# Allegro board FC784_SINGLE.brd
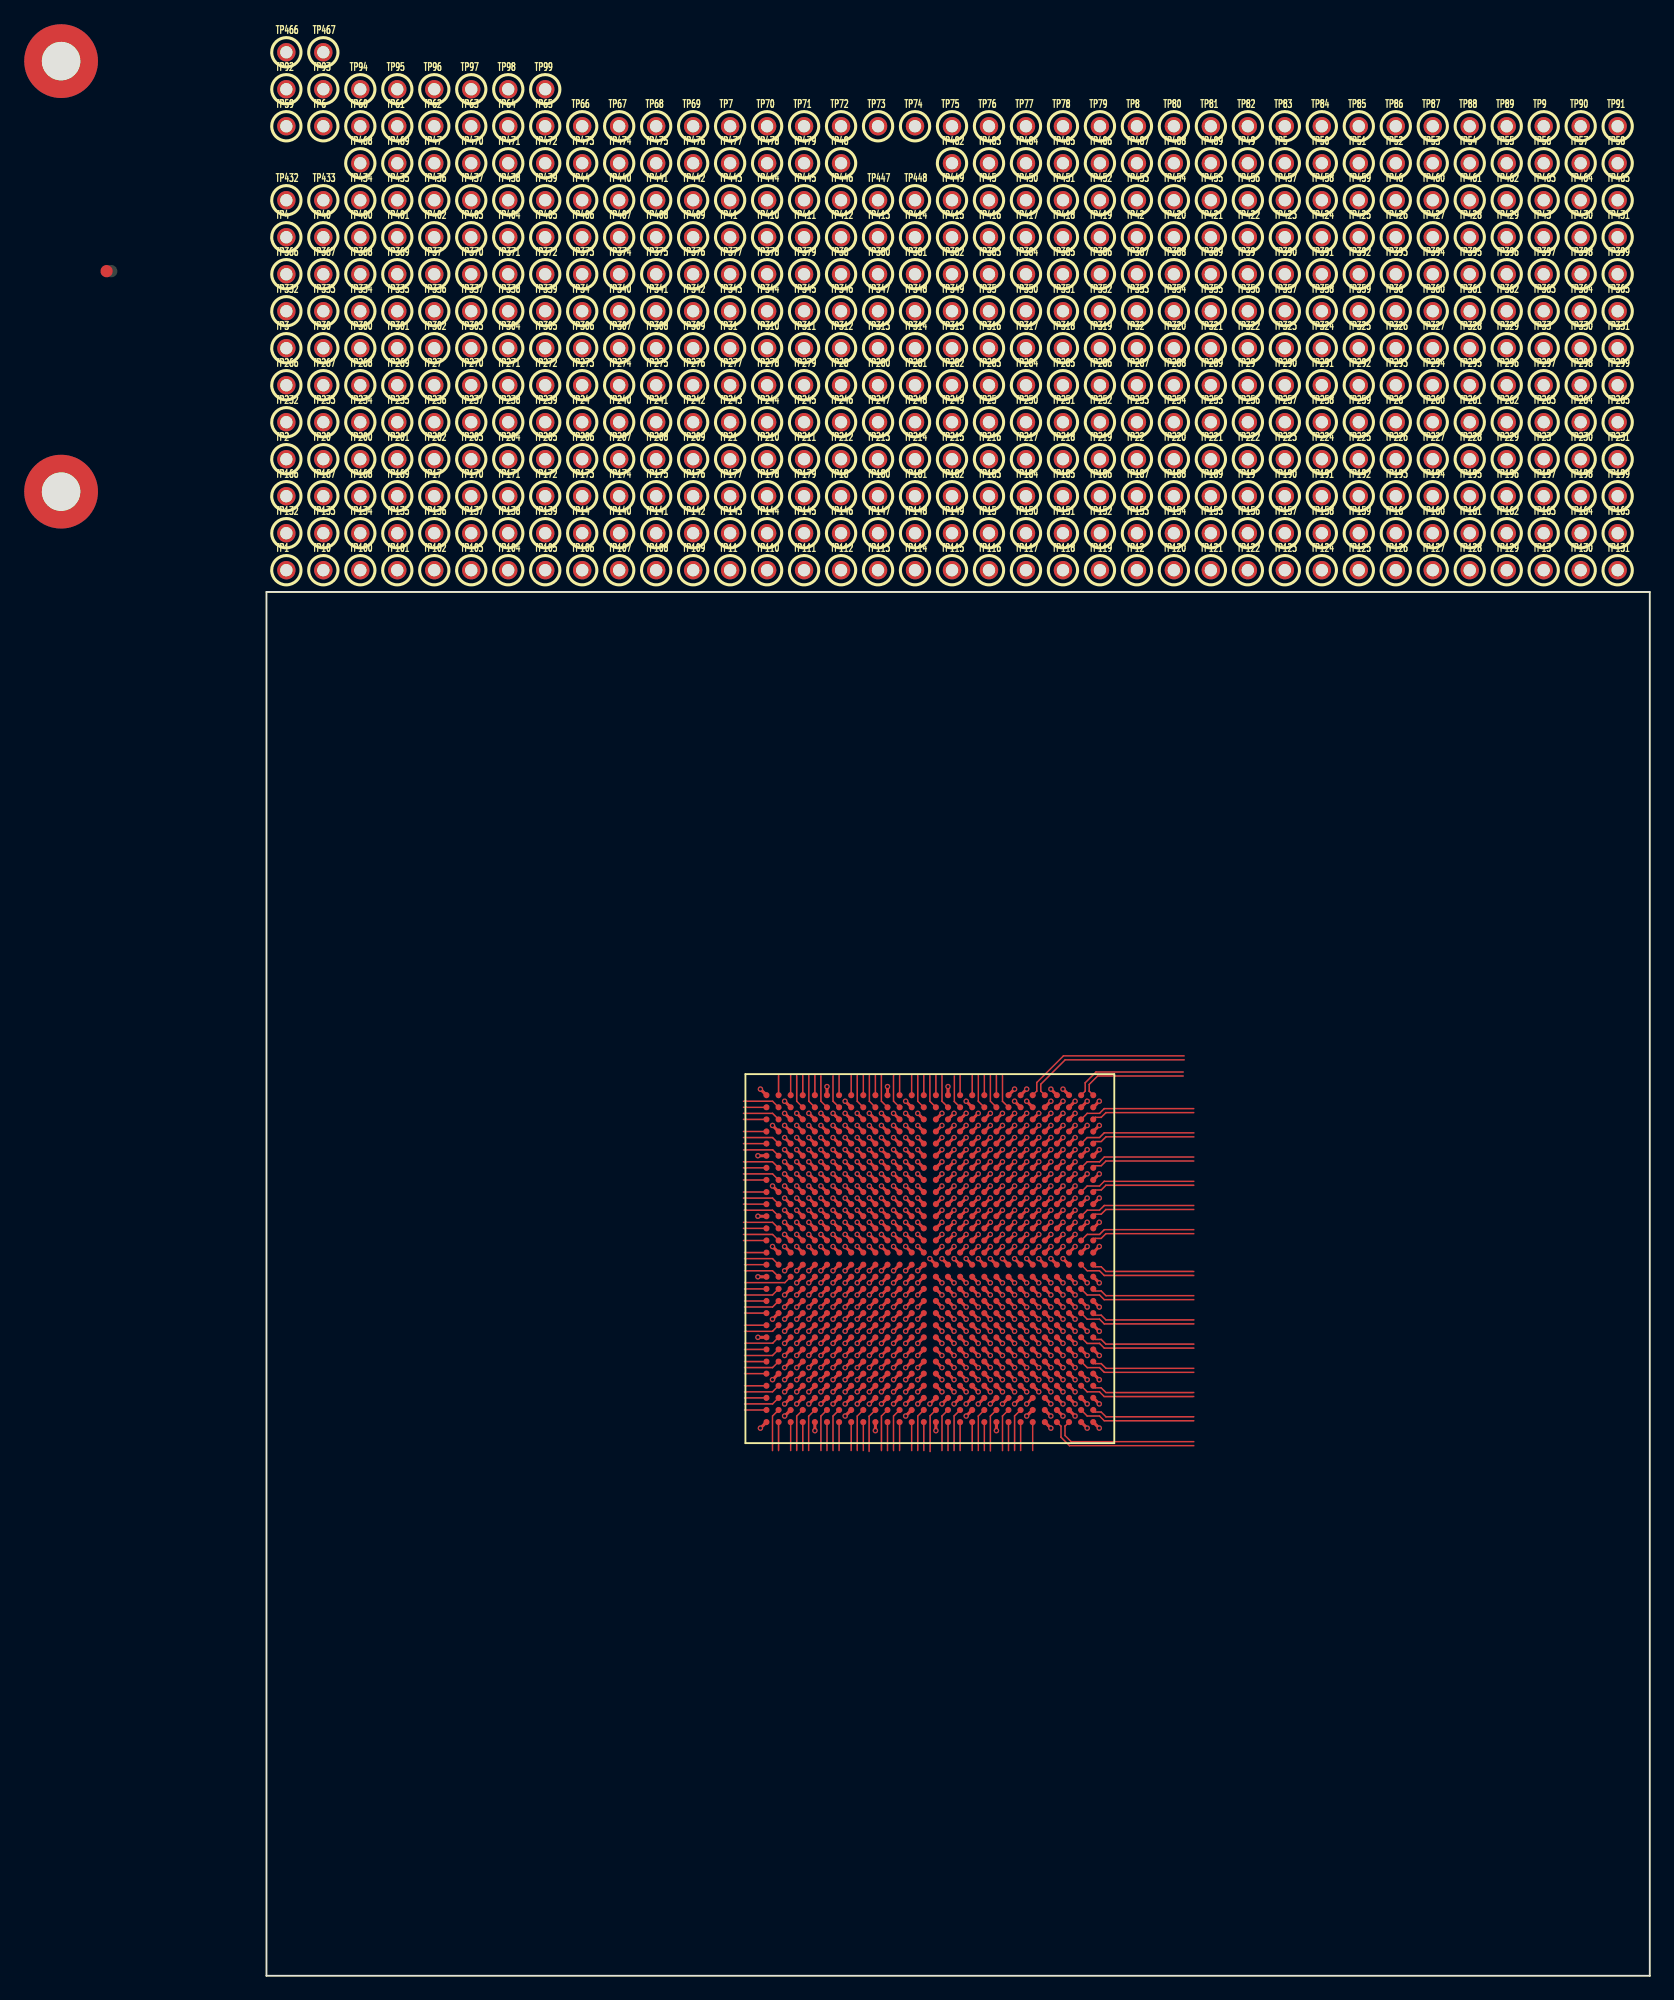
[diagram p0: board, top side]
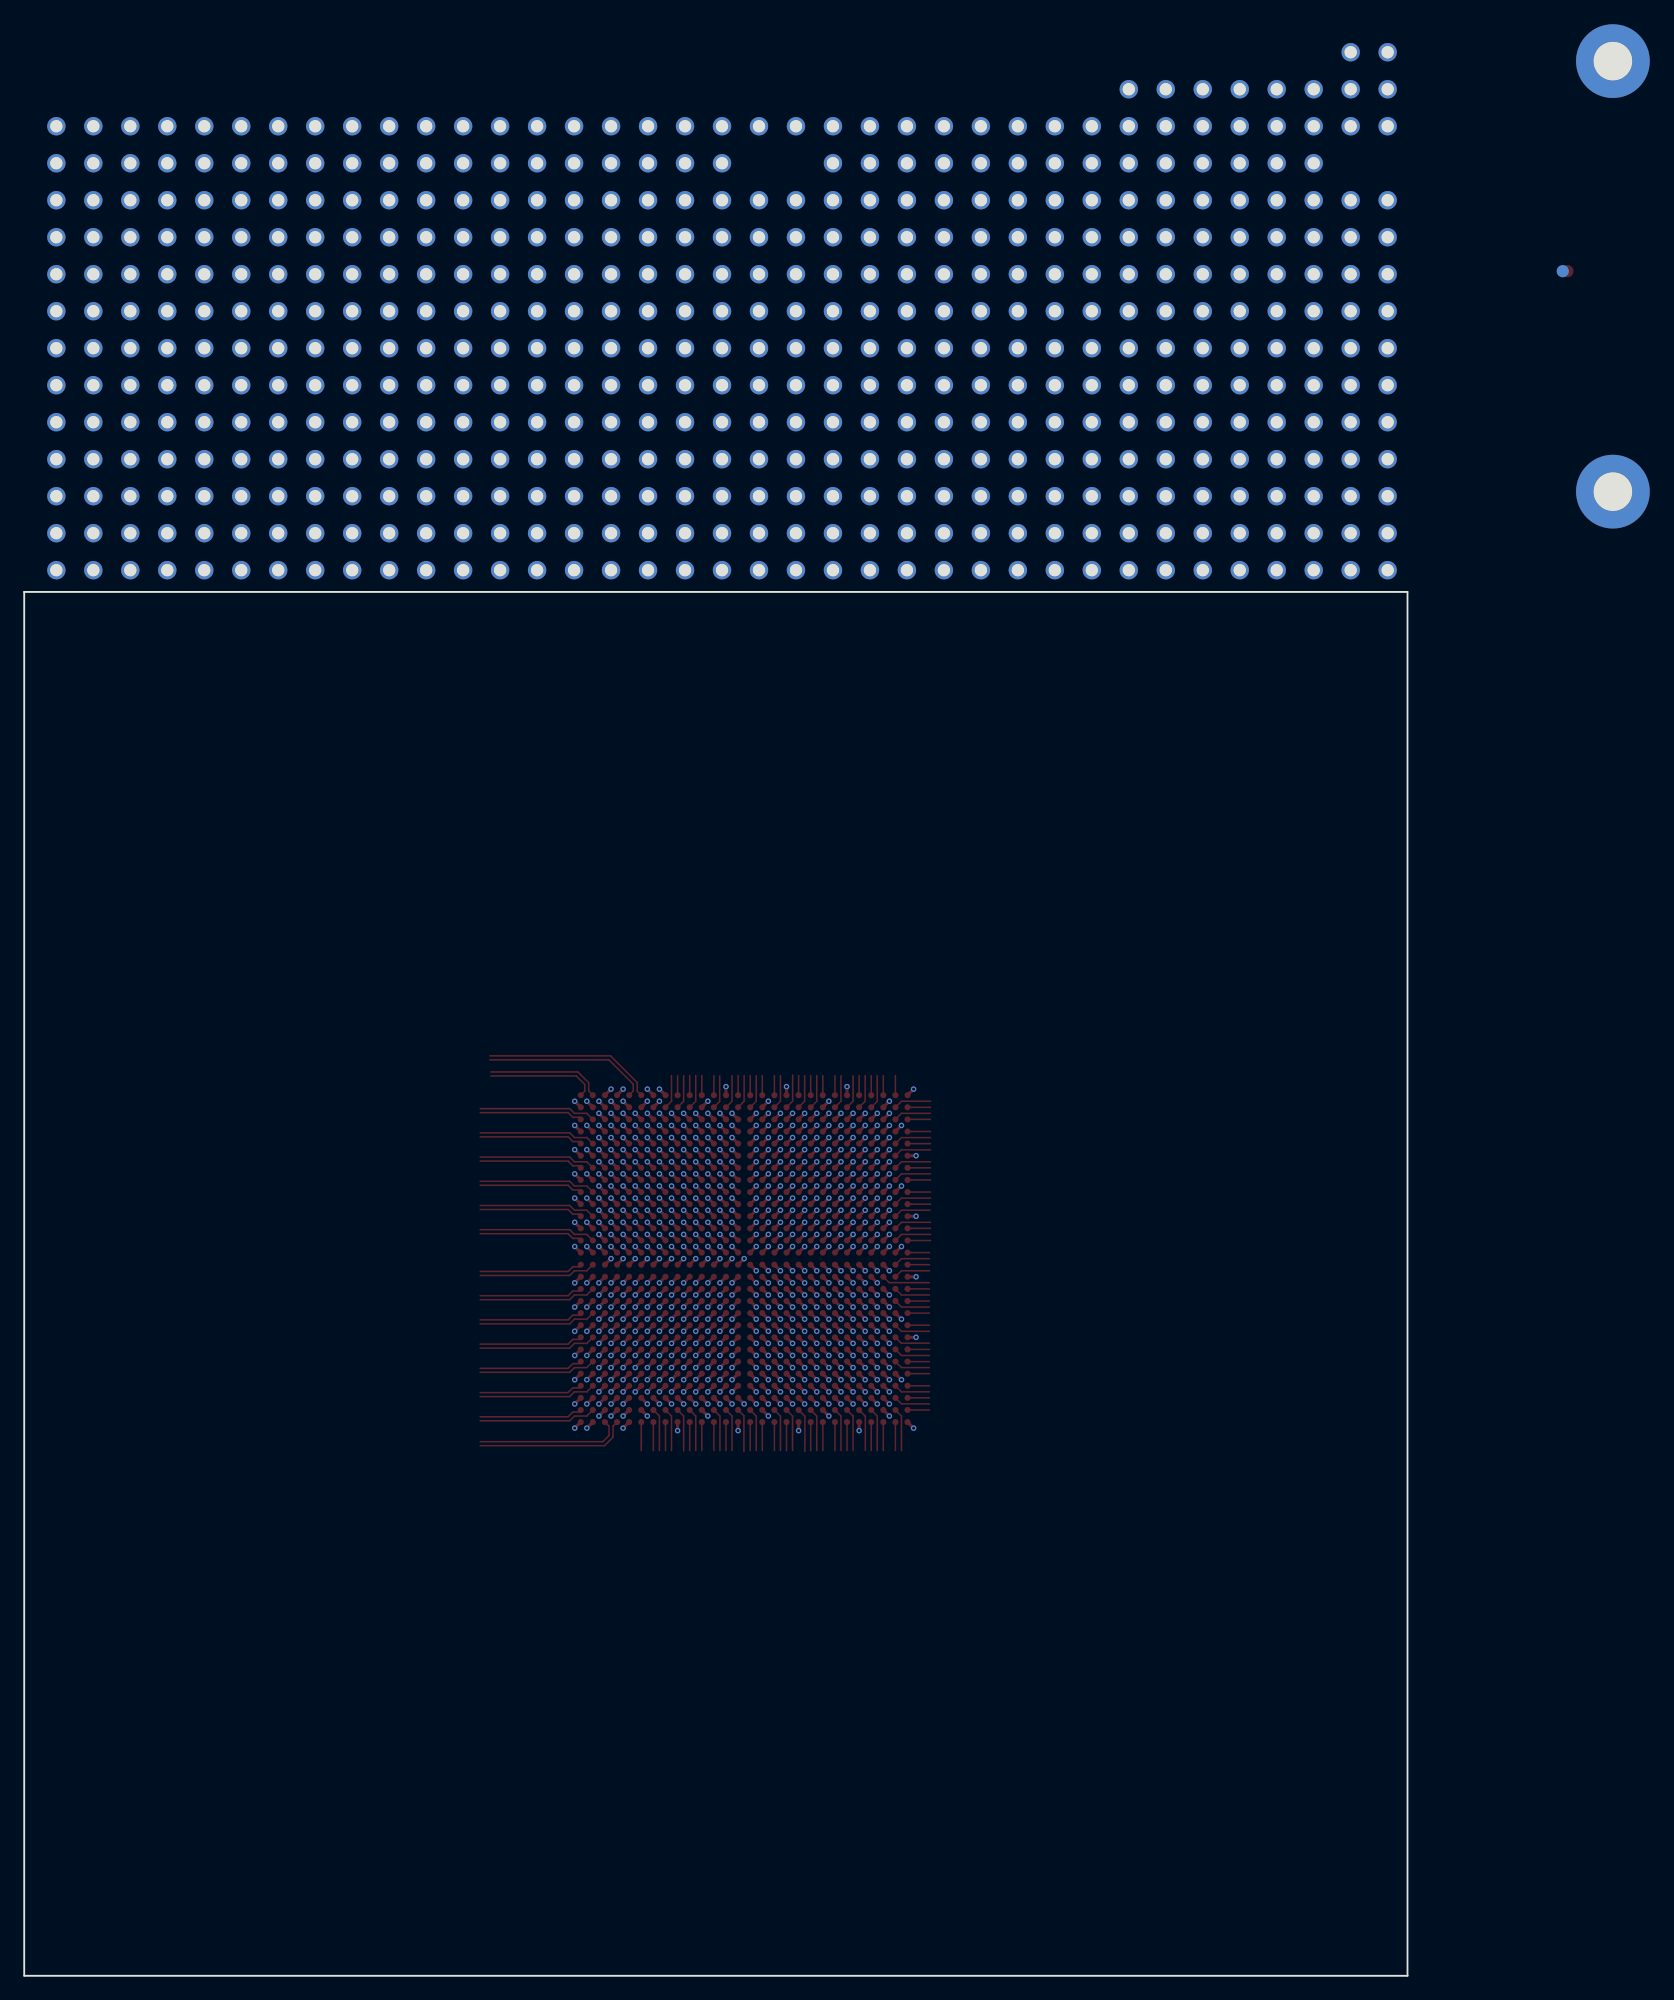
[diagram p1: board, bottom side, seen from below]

Outline 114.3 x 114.3 mm; copper layers: TOP, L2_GND1, L3_SIG1, L4_SIG2, L5_SIG3, L6_SIG4, L7_GND2, BOTTOM. Coordinates in mm from the lower left corner of the outline.
Outline path: 0,114.3 114.3,114.3 114.3,0 0,0 0,114.3

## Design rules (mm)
net group SERDES_0_INT_REFCLK_: nets SERDES_0_INT_REFCLK_N SERDES_0_INT_REFCLK_P
net group SERDES_0_RX0_: nets SERDES_0_RX0_N SERDES_0_RX0_P
net group SERDES_0_RX1_: nets SERDES_0_RX1_N SERDES_0_RX1_P
net group SERDES_0_RX2_: nets SERDES_0_RX2_N SERDES_0_RX2_P
net group SERDES_0_RX3_: nets SERDES_0_RX3_N SERDES_0_RX3_P
net group SERDES_0_TX0_: nets SERDES_0_TX0_N SERDES_0_TX0_P
net group SERDES_0_TX1_: nets SERDES_0_TX1_N SERDES_0_TX1_P
net group SERDES_0_TX2_: nets SERDES_0_TX2_N SERDES_0_TX2_P
net group SERDES_0_TX3_: nets SERDES_0_TX3_N SERDES_0_TX3_P
net group SERDES_0N_EXT_REFCLK_: nets SERDES_0N_EXT_REFCLK_N SERDES_0N_EXT_REFCLK_P
net group SERDES_0S_EXT_REFCLK_: nets SERDES_0S_EXT_REFCLK_N SERDES_0S_EXT_REFCLK_P
net group SERDES_01_EXT_REFCLK_: nets SERDES_01_EXT_REFCLK_N SERDES_01_EXT_REFCLK_P
net group SERDES_1_INT_REFCLK_: nets SERDES_1_INT_REFCLK_N SERDES_1_INT_REFCLK_P
net group SERDES_1_RX0_: nets SERDES_1_RX0_N SERDES_1_RX0_P
net group SERDES_1_RX1_: nets SERDES_1_RX1_N SERDES_1_RX1_P
net group SERDES_1_RX2_: nets SERDES_1_RX2_N SERDES_1_RX2_P
net group SERDES_1_RX3_: nets SERDES_1_RX3_N SERDES_1_RX3_P
net group SERDES_1_TX0_: nets SERDES_1_TX0_N SERDES_1_TX0_P
net group SERDES_1_TX1_: nets SERDES_1_TX1_N SERDES_1_TX1_P
net group SERDES_1_TX2_: nets SERDES_1_TX2_N SERDES_1_TX2_P
net group SERDES_1_TX3_: nets SERDES_1_TX3_N SERDES_1_TX3_P
net group SERDES_02_EXT_REFCLK_: nets SERDES_02_EXT_REFCLK_N SERDES_02_EXT_REFCLK_P
net group SERDES_2_INT_REFCLK_: nets SERDES_2_INT_REFCLK_N SERDES_2_INT_REFCLK_P
net group SERDES_2_RX0_: nets SERDES_2_RX0_N SERDES_2_RX0_P
net group SERDES_2_RX1_: nets SERDES_2_RX1_N SERDES_2_RX1_P
net group SERDES_2_RX2_: nets SERDES_2_RX2_N SERDES_2_RX2_P
net group SERDES_2_RX3_: nets SERDES_2_RX3_N SERDES_2_RX3_P
net group SERDES_2_TX0_: nets SERDES_2_TX0_N SERDES_2_TX0_P
net group SERDES_2_TX1_: nets SERDES_2_TX1_N SERDES_2_TX1_P
net group SERDES_2_TX2_: nets SERDES_2_TX2_N SERDES_2_TX2_P
net group SERDES_2_TX3_: nets SERDES_2_TX3_N SERDES_2_TX3_P
net group SERDES_3_INT_REFCLK_: nets SERDES_3_INT_REFCLK_N SERDES_3_INT_REFCLK_P
net group SERDES_3_RX0_: nets SERDES_3_RX0_N SERDES_3_RX0_P
net group SERDES_3_RX1_: nets SERDES_3_RX1_N SERDES_3_RX1_P
net group SERDES_3_RX2_: nets SERDES_3_RX2_N SERDES_3_RX2_P
net group SERDES_3_RX3_: nets SERDES_3_RX3_N SERDES_3_RX3_P
net group SERDES_3_TX0_: nets SERDES_3_TX0_N SERDES_3_TX0_P
net group SERDES_3_TX1_: nets SERDES_3_TX1_N SERDES_3_TX1_P
net group SERDES_3_TX2_: nets SERDES_3_TX2_N SERDES_3_TX2_P
net group SERDES_3_TX3_: nets SERDES_3_TX3_N SERDES_3_TX3_P
net group SERDES_13_EXT_REFCLK_: nets SERDES_13_EXT_REFCLK_N SERDES_13_EXT_REFCLK_P
net group SERDES_24_EXT_REFCLK_: nets SERDES_24_EXT_REFCLK_N SERDES_24_EXT_REFCLK_P
net group SERDES_35_EXT_REFCLK_: nets SERDES_35_EXT_REFCLK_N SERDES_35_EXT_REFCLK_P

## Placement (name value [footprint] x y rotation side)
NOREF  -  [unnamed]  -16.97 158.14 0 top
NOREF#2  -  [unnamed]  -16.97 122.58 0 top
NOREF#3  -  [unnamed]  -13.21 140.79 0 top
NOREF#4  -  [#2]  306.73 11.62 0 top
NOREF#5  -  [unnamed]  -12.83 140.79 180 bottom
TP1  TP  [TP_40D60]  1.64 116.09 0 top
TP2  TP  [TP_40D60]  1.64 125.26 0 top
TP3  TP  [TP_40D60]  1.64 134.43 0 top
TP4  TP  [TP_40D60]  1.64 143.6 0 top
TP5  TP  [TP_40D60]  84.14 149.71 0 top
TP6  TP  [TP_40D60]  4.7 152.76 0 top
TP7  TP  [TP_40D60]  38.31 152.76 0 top
TP8  TP  [TP_40D60]  71.92 152.76 0 top
TP9  TP  [TP_40D60]  105.53 152.76 0 top
TP10  TP  [TP_40D60]  4.7 116.09 0 top
TP11  TP  [TP_40D60]  38.31 116.09 0 top
TP12  TP  [TP_40D60]  71.92 116.09 0 top
TP13  TP  [TP_40D60]  105.53 116.09 0 top
TP14  TP  [TP_40D60]  26.09 119.15 0 top
TP15  TP  [TP_40D60]  59.7 119.15 0 top
TP16  TP  [TP_40D60]  93.31 119.15 0 top
TP17  TP  [TP_40D60]  13.86 122.21 0 top
TP18  TP  [TP_40D60]  47.48 122.21 0 top
TP19  TP  [TP_40D60]  81.09 122.21 0 top
TP20  TP  [TP_40D60]  4.7 125.26 0 top
TP21  TP  [TP_40D60]  38.31 125.26 0 top
TP22  TP  [TP_40D60]  71.92 125.26 0 top
TP23  TP  [TP_40D60]  105.53 125.26 0 top
TP24  TP  [TP_40D60]  26.09 128.32 0 top
TP25  TP  [TP_40D60]  59.7 128.32 0 top
TP26  TP  [TP_40D60]  93.31 128.32 0 top
TP27  TP  [TP_40D60]  13.86 131.37 0 top
TP28  TP  [TP_40D60]  47.48 131.37 0 top
TP29  TP  [TP_40D60]  81.09 131.37 0 top
TP30  TP  [TP_40D60]  4.7 134.43 0 top
TP31  TP  [TP_40D60]  38.31 134.43 0 top
TP32  TP  [TP_40D60]  71.92 134.43 0 top
TP33  TP  [TP_40D60]  105.53 134.43 0 top
TP34  TP  [TP_40D60]  26.09 137.48 0 top
TP35  TP  [TP_40D60]  59.7 137.48 0 top
TP36  TP  [TP_40D60]  93.31 137.48 0 top
TP37  TP  [TP_40D60]  13.86 140.54 0 top
TP38  TP  [TP_40D60]  47.48 140.54 0 top
TP39  TP  [TP_40D60]  81.09 140.54 0 top
TP40  TP  [TP_40D60]  4.7 143.6 0 top
TP41  TP  [TP_40D60]  38.31 143.6 0 top
TP42  TP  [TP_40D60]  71.92 143.6 0 top
TP43  TP  [TP_40D60]  105.53 143.6 0 top
TP44  TP  [TP_40D60]  26.09 146.65 0 top
TP45  TP  [TP_40D60]  59.7 146.65 0 top
TP46  TP  [TP_40D60]  93.31 146.65 0 top
TP47  TP  [TP_40D60]  13.86 149.71 0 top
TP48  TP  [TP_40D60]  47.48 149.71 0 top
TP49  TP  [TP_40D60]  81.09 149.71 0 top
TP50  TP  [TP_40D60]  87.2 149.71 0 top
TP51  TP  [TP_40D60]  90.26 149.71 0 top
TP52  TP  [TP_40D60]  93.31 149.71 0 top
TP53  TP  [TP_40D60]  96.37 149.71 0 top
TP54  TP  [TP_40D60]  99.42 149.71 0 top
TP55  TP  [TP_40D60]  102.48 149.71 0 top
TP56  TP  [TP_40D60]  105.53 149.71 0 top
TP57  TP  [TP_40D60]  108.59 149.71 0 top
TP58  TP  [TP_40D60]  111.64 149.71 0 top
TP59  TP  [TP_40D60]  1.64 152.76 0 top
TP60  TP  [TP_40D60]  7.75 152.76 0 top
TP61  TP  [TP_40D60]  10.81 152.76 0 top
TP62  TP  [TP_40D60]  13.86 152.76 0 top
TP63  TP  [TP_40D60]  16.92 152.76 0 top
TP64  TP  [TP_40D60]  19.98 152.76 0 top
TP65  TP  [TP_40D60]  23.03 152.76 0 top
TP66  TP  [TP_40D60]  26.09 152.76 0 top
TP67  TP  [TP_40D60]  29.14 152.76 0 top
TP68  TP  [TP_40D60]  32.2 152.76 0 top
TP69  TP  [TP_40D60]  35.25 152.76 0 top
TP70  TP  [TP_40D60]  41.37 152.76 0 top
TP71  TP  [TP_40D60]  44.42 152.76 0 top
TP72  TP  [TP_40D60]  47.48 152.76 0 top
TP73  TP  [TP_40D60]  50.53 152.76 0 top
TP74  TP  [TP_40D60]  53.59 152.76 0 top
TP75  TP  [TP_40D60]  56.64 152.76 0 top
TP76  TP  [TP_40D60]  59.7 152.76 0 top
TP77  TP  [TP_40D60]  62.75 152.76 0 top
TP78  TP  [TP_40D60]  65.81 152.76 0 top
TP79  TP  [TP_40D60]  68.87 152.76 0 top
TP80  TP  [TP_40D60]  74.98 152.76 0 top
TP81  TP  [TP_40D60]  78.03 152.76 0 top
TP82  TP  [TP_40D60]  81.09 152.76 0 top
TP83  TP  [TP_40D60]  84.14 152.76 0 top
TP84  TP  [TP_40D60]  87.2 152.76 0 top
TP85  TP  [TP_40D60]  90.26 152.76 0 top
TP86  TP  [TP_40D60]  93.31 152.76 0 top
TP87  TP  [TP_40D60]  96.37 152.76 0 top
TP88  TP  [TP_40D60]  99.42 152.76 0 top
TP89  TP  [TP_40D60]  102.48 152.76 0 top
TP90  TP  [TP_40D60]  108.59 152.76 0 top
TP91  TP  [TP_40D60]  111.64 152.76 0 top
TP92  TP  [TP_40D60]  1.64 155.82 0 top
TP93  TP  [TP_40D60]  4.7 155.82 0 top
TP94  TP  [TP_40D60]  7.75 155.82 0 top
TP95  TP  [TP_40D60]  10.81 155.82 0 top
TP96  TP  [TP_40D60]  13.86 155.82 0 top
TP97  TP  [TP_40D60]  16.92 155.82 0 top
TP98  TP  [TP_40D60]  19.98 155.82 0 top
TP99  TP  [TP_40D60]  23.03 155.82 0 top
TP100  TP  [TP_40D60]  7.75 116.09 0 top
TP101  TP  [TP_40D60]  10.81 116.09 0 top
TP102  TP  [TP_40D60]  13.86 116.09 0 top
TP103  TP  [TP_40D60]  16.92 116.09 0 top
TP104  TP  [TP_40D60]  19.98 116.09 0 top
TP105  TP  [TP_40D60]  23.03 116.09 0 top
TP106  TP  [TP_40D60]  26.09 116.09 0 top
TP107  TP  [TP_40D60]  29.14 116.09 0 top
TP108  TP  [TP_40D60]  32.2 116.09 0 top
TP109  TP  [TP_40D60]  35.25 116.09 0 top
TP110  TP  [TP_40D60]  41.37 116.09 0 top
TP111  TP  [TP_40D60]  44.42 116.09 0 top
TP112  TP  [TP_40D60]  47.48 116.09 0 top
TP113  TP  [TP_40D60]  50.53 116.09 0 top
TP114  TP  [TP_40D60]  53.59 116.09 0 top
TP115  TP  [TP_40D60]  56.64 116.09 0 top
TP116  TP  [TP_40D60]  59.7 116.09 0 top
TP117  TP  [TP_40D60]  62.75 116.09 0 top
TP118  TP  [TP_40D60]  65.81 116.09 0 top
TP119  TP  [TP_40D60]  68.87 116.09 0 top
TP120  TP  [TP_40D60]  74.98 116.09 0 top
TP121  TP  [TP_40D60]  78.03 116.09 0 top
TP122  TP  [TP_40D60]  81.09 116.09 0 top
TP123  TP  [TP_40D60]  84.14 116.09 0 top
TP124  TP  [TP_40D60]  87.2 116.09 0 top
TP125  TP  [TP_40D60]  90.26 116.09 0 top
TP126  TP  [TP_40D60]  93.31 116.09 0 top
TP127  TP  [TP_40D60]  96.37 116.09 0 top
TP128  TP  [TP_40D60]  99.42 116.09 0 top
TP129  TP  [TP_40D60]  102.48 116.09 0 top
TP130  TP  [TP_40D60]  108.59 116.09 0 top
TP131  TP  [TP_40D60]  111.64 116.09 0 top
TP132  TP  [TP_40D60]  1.64 119.15 0 top
TP133  TP  [TP_40D60]  4.7 119.15 0 top
TP134  TP  [TP_40D60]  7.75 119.15 0 top
TP135  TP  [TP_40D60]  10.81 119.15 0 top
TP136  TP  [TP_40D60]  13.86 119.15 0 top
TP137  TP  [TP_40D60]  16.92 119.15 0 top
TP138  TP  [TP_40D60]  19.98 119.15 0 top
TP139  TP  [TP_40D60]  23.03 119.15 0 top
TP140  TP  [TP_40D60]  29.14 119.15 0 top
TP141  TP  [TP_40D60]  32.2 119.15 0 top
TP142  TP  [TP_40D60]  35.25 119.15 0 top
TP143  TP  [TP_40D60]  38.31 119.15 0 top
TP144  TP  [TP_40D60]  41.37 119.15 0 top
TP145  TP  [TP_40D60]  44.42 119.15 0 top
TP146  TP  [TP_40D60]  47.48 119.15 0 top
TP147  TP  [TP_40D60]  50.53 119.15 0 top
TP148  TP  [TP_40D60]  53.59 119.15 0 top
TP149  TP  [TP_40D60]  56.64 119.15 0 top
TP150  TP  [TP_40D60]  62.75 119.15 0 top
TP151  TP  [TP_40D60]  65.81 119.15 0 top
TP152  TP  [TP_40D60]  68.87 119.15 0 top
TP153  TP  [TP_40D60]  71.92 119.15 0 top
TP154  TP  [TP_40D60]  74.98 119.15 0 top
TP155  TP  [TP_40D60]  78.03 119.15 0 top
TP156  TP  [TP_40D60]  81.09 119.15 0 top
TP157  TP  [TP_40D60]  84.14 119.15 0 top
TP158  TP  [TP_40D60]  87.2 119.15 0 top
TP159  TP  [TP_40D60]  90.26 119.15 0 top
TP160  TP  [TP_40D60]  96.37 119.15 0 top
TP161  TP  [TP_40D60]  99.42 119.15 0 top
TP162  TP  [TP_40D60]  102.48 119.15 0 top
TP163  TP  [TP_40D60]  105.53 119.15 0 top
TP164  TP  [TP_40D60]  108.59 119.15 0 top
TP165  TP  [TP_40D60]  111.64 119.15 0 top
TP166  TP  [TP_40D60]  1.64 122.21 0 top
TP167  TP  [TP_40D60]  4.7 122.21 0 top
TP168  TP  [TP_40D60]  7.75 122.21 0 top
TP169  TP  [TP_40D60]  10.81 122.21 0 top
TP170  TP  [TP_40D60]  16.92 122.21 0 top
TP171  TP  [TP_40D60]  19.98 122.21 0 top
TP172  TP  [TP_40D60]  23.03 122.21 0 top
TP173  TP  [TP_40D60]  26.09 122.21 0 top
TP174  TP  [TP_40D60]  29.14 122.21 0 top
TP175  TP  [TP_40D60]  32.2 122.21 0 top
TP176  TP  [TP_40D60]  35.25 122.21 0 top
TP177  TP  [TP_40D60]  38.31 122.21 0 top
TP178  TP  [TP_40D60]  41.37 122.21 0 top
TP179  TP  [TP_40D60]  44.42 122.21 0 top
TP180  TP  [TP_40D60]  50.53 122.21 0 top
TP181  TP  [TP_40D60]  53.59 122.21 0 top
TP182  TP  [TP_40D60]  56.64 122.21 0 top
TP183  TP  [TP_40D60]  59.7 122.21 0 top
TP184  TP  [TP_40D60]  62.75 122.21 0 top
TP185  TP  [TP_40D60]  65.81 122.21 0 top
TP186  TP  [TP_40D60]  68.87 122.21 0 top
TP187  TP  [TP_40D60]  71.92 122.21 0 top
TP188  TP  [TP_40D60]  74.98 122.21 0 top
TP189  TP  [TP_40D60]  78.03 122.21 0 top
TP190  TP  [TP_40D60]  84.14 122.21 0 top
TP191  TP  [TP_40D60]  87.2 122.21 0 top
TP192  TP  [TP_40D60]  90.26 122.21 0 top
TP193  TP  [TP_40D60]  93.31 122.21 0 top
TP194  TP  [TP_40D60]  96.37 122.21 0 top
TP195  TP  [TP_40D60]  99.42 122.21 0 top
TP196  TP  [TP_40D60]  102.48 122.21 0 top
TP197  TP  [TP_40D60]  105.53 122.21 0 top
TP198  TP  [TP_40D60]  108.59 122.21 0 top
TP199  TP  [TP_40D60]  111.64 122.21 0 top
TP200  TP  [TP_40D60]  7.75 125.26 0 top
TP201  TP  [TP_40D60]  10.81 125.26 0 top
TP202  TP  [TP_40D60]  13.86 125.26 0 top
TP203  TP  [TP_40D60]  16.92 125.26 0 top
TP204  TP  [TP_40D60]  19.98 125.26 0 top
TP205  TP  [TP_40D60]  23.03 125.26 0 top
TP206  TP  [TP_40D60]  26.09 125.26 0 top
TP207  TP  [TP_40D60]  29.14 125.26 0 top
TP208  TP  [TP_40D60]  32.2 125.26 0 top
TP209  TP  [TP_40D60]  35.25 125.26 0 top
TP210  TP  [TP_40D60]  41.37 125.26 0 top
TP211  TP  [TP_40D60]  44.42 125.26 0 top
TP212  TP  [TP_40D60]  47.48 125.26 0 top
TP213  TP  [TP_40D60]  50.53 125.26 0 top
TP214  TP  [TP_40D60]  53.59 125.26 0 top
TP215  TP  [TP_40D60]  56.64 125.26 0 top
TP216  TP  [TP_40D60]  59.7 125.26 0 top
TP217  TP  [TP_40D60]  62.75 125.26 0 top
TP218  TP  [TP_40D60]  65.81 125.26 0 top
TP219  TP  [TP_40D60]  68.87 125.26 0 top
TP220  TP  [TP_40D60]  74.98 125.26 0 top
TP221  TP  [TP_40D60]  78.03 125.26 0 top
TP222  TP  [TP_40D60]  81.09 125.26 0 top
TP223  TP  [TP_40D60]  84.14 125.26 0 top
TP224  TP  [TP_40D60]  87.2 125.26 0 top
TP225  TP  [TP_40D60]  90.26 125.26 0 top
TP226  TP  [TP_40D60]  93.31 125.26 0 top
TP227  TP  [TP_40D60]  96.37 125.26 0 top
TP228  TP  [TP_40D60]  99.42 125.26 0 top
TP229  TP  [TP_40D60]  102.48 125.26 0 top
TP230  TP  [TP_40D60]  108.59 125.26 0 top
TP231  TP  [TP_40D60]  111.64 125.26 0 top
TP232  TP  [TP_40D60]  1.64 128.32 0 top
TP233  TP  [TP_40D60]  4.7 128.32 0 top
TP234  TP  [TP_40D60]  7.75 128.32 0 top
TP235  TP  [TP_40D60]  10.81 128.32 0 top
TP236  TP  [TP_40D60]  13.86 128.32 0 top
TP237  TP  [TP_40D60]  16.92 128.32 0 top
TP238  TP  [TP_40D60]  19.98 128.32 0 top
TP239  TP  [TP_40D60]  23.03 128.32 0 top
TP240  TP  [TP_40D60]  29.14 128.32 0 top
TP241  TP  [TP_40D60]  32.2 128.32 0 top
TP242  TP  [TP_40D60]  35.25 128.32 0 top
TP243  TP  [TP_40D60]  38.31 128.32 0 top
TP244  TP  [TP_40D60]  41.37 128.32 0 top
TP245  TP  [TP_40D60]  44.42 128.32 0 top
TP246  TP  [TP_40D60]  47.48 128.32 0 top
TP247  TP  [TP_40D60]  50.53 128.32 0 top
TP248  TP  [TP_40D60]  53.59 128.32 0 top
TP249  TP  [TP_40D60]  56.64 128.32 0 top
TP250  TP  [TP_40D60]  62.75 128.32 0 top
TP251  TP  [TP_40D60]  65.81 128.32 0 top
TP252  TP  [TP_40D60]  68.87 128.32 0 top
TP253  TP  [TP_40D60]  71.92 128.32 0 top
TP254  TP  [TP_40D60]  74.98 128.32 0 top
TP255  TP  [TP_40D60]  78.03 128.32 0 top
TP256  TP  [TP_40D60]  81.09 128.32 0 top
TP257  TP  [TP_40D60]  84.14 128.32 0 top
TP258  TP  [TP_40D60]  87.2 128.32 0 top
TP259  TP  [TP_40D60]  90.26 128.32 0 top
TP260  TP  [TP_40D60]  96.37 128.32 0 top
TP261  TP  [TP_40D60]  99.42 128.32 0 top
TP262  TP  [TP_40D60]  102.48 128.32 0 top
TP263  TP  [TP_40D60]  105.53 128.32 0 top
TP264  TP  [TP_40D60]  108.59 128.32 0 top
TP265  TP  [TP_40D60]  111.64 128.32 0 top
TP266  TP  [TP_40D60]  1.64 131.37 0 top
TP267  TP  [TP_40D60]  4.7 131.37 0 top
TP268  TP  [TP_40D60]  7.75 131.37 0 top
TP269  TP  [TP_40D60]  10.81 131.37 0 top
TP270  TP  [TP_40D60]  16.92 131.37 0 top
TP271  TP  [TP_40D60]  19.98 131.37 0 top
TP272  TP  [TP_40D60]  23.03 131.37 0 top
TP273  TP  [TP_40D60]  26.09 131.37 0 top
TP274  TP  [TP_40D60]  29.14 131.37 0 top
TP275  TP  [TP_40D60]  32.2 131.37 0 top
TP276  TP  [TP_40D60]  35.25 131.37 0 top
TP277  TP  [TP_40D60]  38.31 131.37 0 top
TP278  TP  [TP_40D60]  41.37 131.37 0 top
TP279  TP  [TP_40D60]  44.42 131.37 0 top
TP280  TP  [TP_40D60]  50.53 131.37 0 top
TP281  TP  [TP_40D60]  53.59 131.37 0 top
TP282  TP  [TP_40D60]  56.64 131.37 0 top
TP283  TP  [TP_40D60]  59.7 131.37 0 top
TP284  TP  [TP_40D60]  62.75 131.37 0 top
TP285  TP  [TP_40D60]  65.81 131.37 0 top
TP286  TP  [TP_40D60]  68.87 131.37 0 top
TP287  TP  [TP_40D60]  71.92 131.37 0 top
TP288  TP  [TP_40D60]  74.98 131.37 0 top
TP289  TP  [TP_40D60]  78.03 131.37 0 top
TP290  TP  [TP_40D60]  84.14 131.37 0 top
TP291  TP  [TP_40D60]  87.2 131.37 0 top
TP292  TP  [TP_40D60]  90.26 131.37 0 top
TP293  TP  [TP_40D60]  93.31 131.37 0 top
TP294  TP  [TP_40D60]  96.37 131.37 0 top
TP295  TP  [TP_40D60]  99.42 131.37 0 top
TP296  TP  [TP_40D60]  102.48 131.37 0 top
TP297  TP  [TP_40D60]  105.53 131.37 0 top
TP298  TP  [TP_40D60]  108.59 131.37 0 top
TP299  TP  [TP_40D60]  111.64 131.37 0 top
TP300  TP  [TP_40D60]  7.75 134.43 0 top
TP301  TP  [TP_40D60]  10.81 134.43 0 top
TP302  TP  [TP_40D60]  13.86 134.43 0 top
TP303  TP  [TP_40D60]  16.92 134.43 0 top
TP304  TP  [TP_40D60]  19.98 134.43 0 top
TP305  TP  [TP_40D60]  23.03 134.43 0 top
TP306  TP  [TP_40D60]  26.09 134.43 0 top
TP307  TP  [TP_40D60]  29.14 134.43 0 top
TP308  TP  [TP_40D60]  32.2 134.43 0 top
TP309  TP  [TP_40D60]  35.25 134.43 0 top
TP310  TP  [TP_40D60]  41.37 134.43 0 top
TP311  TP  [TP_40D60]  44.42 134.43 0 top
TP312  TP  [TP_40D60]  47.48 134.43 0 top
TP313  TP  [TP_40D60]  50.53 134.43 0 top
TP314  TP  [TP_40D60]  53.59 134.43 0 top
TP315  TP  [TP_40D60]  56.64 134.43 0 top
TP316  TP  [TP_40D60]  59.7 134.43 0 top
TP317  TP  [TP_40D60]  62.75 134.43 0 top
TP318  TP  [TP_40D60]  65.81 134.43 0 top
TP319  TP  [TP_40D60]  68.87 134.43 0 top
TP320  TP  [TP_40D60]  74.98 134.43 0 top
TP321  TP  [TP_40D60]  78.03 134.43 0 top
TP322  TP  [TP_40D60]  81.09 134.43 0 top
TP323  TP  [TP_40D60]  84.14 134.43 0 top
TP324  TP  [TP_40D60]  87.2 134.43 0 top
TP325  TP  [TP_40D60]  90.26 134.43 0 top
TP326  TP  [TP_40D60]  93.31 134.43 0 top
TP327  TP  [TP_40D60]  96.37 134.43 0 top
TP328  TP  [TP_40D60]  99.42 134.43 0 top
TP329  TP  [TP_40D60]  102.48 134.43 0 top
TP330  TP  [TP_40D60]  108.59 134.43 0 top
TP331  TP  [TP_40D60]  111.64 134.43 0 top
TP332  TP  [TP_40D60]  1.64 137.48 0 top
TP333  TP  [TP_40D60]  4.7 137.48 0 top
TP334  TP  [TP_40D60]  7.75 137.48 0 top
TP335  TP  [TP_40D60]  10.81 137.48 0 top
TP336  TP  [TP_40D60]  13.86 137.48 0 top
TP337  TP  [TP_40D60]  16.92 137.48 0 top
TP338  TP  [TP_40D60]  19.98 137.48 0 top
TP339  TP  [TP_40D60]  23.03 137.48 0 top
TP340  TP  [TP_40D60]  29.14 137.48 0 top
TP341  TP  [TP_40D60]  32.2 137.48 0 top
TP342  TP  [TP_40D60]  35.25 137.48 0 top
TP343  TP  [TP_40D60]  38.31 137.48 0 top
TP344  TP  [TP_40D60]  41.37 137.48 0 top
TP345  TP  [TP_40D60]  44.42 137.48 0 top
TP346  TP  [TP_40D60]  47.48 137.48 0 top
TP347  TP  [TP_40D60]  50.53 137.48 0 top
TP348  TP  [TP_40D60]  53.59 137.48 0 top
TP349  TP  [TP_40D60]  56.64 137.48 0 top
TP350  TP  [TP_40D60]  62.75 137.48 0 top
TP351  TP  [TP_40D60]  65.81 137.48 0 top
TP352  TP  [TP_40D60]  68.87 137.48 0 top
TP353  TP  [TP_40D60]  71.92 137.48 0 top
TP354  TP  [TP_40D60]  74.98 137.48 0 top
TP355  TP  [TP_40D60]  78.03 137.48 0 top
TP356  TP  [TP_40D60]  81.09 137.48 0 top
TP357  TP  [TP_40D60]  84.14 137.48 0 top
TP358  TP  [TP_40D60]  87.2 137.48 0 top
TP359  TP  [TP_40D60]  90.26 137.48 0 top
TP360  TP  [TP_40D60]  96.37 137.48 0 top
TP361  TP  [TP_40D60]  99.42 137.48 0 top
TP362  TP  [TP_40D60]  102.48 137.48 0 top
TP363  TP  [TP_40D60]  105.53 137.48 0 top
TP364  TP  [TP_40D60]  108.59 137.48 0 top
TP365  TP  [TP_40D60]  111.64 137.48 0 top
TP366  TP  [TP_40D60]  1.64 140.54 0 top
TP367  TP  [TP_40D60]  4.7 140.54 0 top
TP368  TP  [TP_40D60]  7.75 140.54 0 top
TP369  TP  [TP_40D60]  10.81 140.54 0 top
TP370  TP  [TP_40D60]  16.92 140.54 0 top
TP371  TP  [TP_40D60]  19.98 140.54 0 top
TP372  TP  [TP_40D60]  23.03 140.54 0 top
TP373  TP  [TP_40D60]  26.09 140.54 0 top
TP374  TP  [TP_40D60]  29.14 140.54 0 top
TP375  TP  [TP_40D60]  32.2 140.54 0 top
TP376  TP  [TP_40D60]  35.25 140.54 0 top
TP377  TP  [TP_40D60]  38.31 140.54 0 top
TP378  TP  [TP_40D60]  41.37 140.54 0 top
TP379  TP  [TP_40D60]  44.42 140.54 0 top
TP380  TP  [TP_40D60]  50.53 140.54 0 top
TP381  TP  [TP_40D60]  53.59 140.54 0 top
TP382  TP  [TP_40D60]  56.64 140.54 0 top
TP383  TP  [TP_40D60]  59.7 140.54 0 top
TP384  TP  [TP_40D60]  62.75 140.54 0 top
TP385  TP  [TP_40D60]  65.81 140.54 0 top
TP386  TP  [TP_40D60]  68.87 140.54 0 top
TP387  TP  [TP_40D60]  71.92 140.54 0 top
TP388  TP  [TP_40D60]  74.98 140.54 0 top
TP389  TP  [TP_40D60]  78.03 140.54 0 top
TP390  TP  [TP_40D60]  84.14 140.54 0 top
TP391  TP  [TP_40D60]  87.2 140.54 0 top
TP392  TP  [TP_40D60]  90.26 140.54 0 top
TP393  TP  [TP_40D60]  93.31 140.54 0 top
TP394  TP  [TP_40D60]  96.37 140.54 0 top
TP395  TP  [TP_40D60]  99.42 140.54 0 top
TP396  TP  [TP_40D60]  102.48 140.54 0 top
TP397  TP  [TP_40D60]  105.53 140.54 0 top
TP398  TP  [TP_40D60]  108.59 140.54 0 top
TP399  TP  [TP_40D60]  111.64 140.54 0 top
TP400  TP  [TP_40D60]  7.75 143.6 0 top
TP401  TP  [TP_40D60]  10.81 143.6 0 top
TP402  TP  [TP_40D60]  13.86 143.6 0 top
TP403  TP  [TP_40D60]  16.92 143.6 0 top
TP404  TP  [TP_40D60]  19.98 143.6 0 top
TP405  TP  [TP_40D60]  23.03 143.6 0 top
TP406  TP  [TP_40D60]  26.09 143.6 0 top
TP407  TP  [TP_40D60]  29.14 143.6 0 top
TP408  TP  [TP_40D60]  32.2 143.6 0 top
TP409  TP  [TP_40D60]  35.25 143.6 0 top
TP410  TP  [TP_40D60]  41.37 143.6 0 top
TP411  TP  [TP_40D60]  44.42 143.6 0 top
TP412  TP  [TP_40D60]  47.48 143.6 0 top
TP413  TP  [TP_40D60]  50.53 143.6 0 top
TP414  TP  [TP_40D60]  53.59 143.6 0 top
TP415  TP  [TP_40D60]  56.64 143.6 0 top
TP416  TP  [TP_40D60]  59.7 143.6 0 top
TP417  TP  [TP_40D60]  62.75 143.6 0 top
TP418  TP  [TP_40D60]  65.81 143.6 0 top
TP419  TP  [TP_40D60]  68.87 143.6 0 top
TP420  TP  [TP_40D60]  74.98 143.6 0 top
TP421  TP  [TP_40D60]  78.03 143.6 0 top
TP422  TP  [TP_40D60]  81.09 143.6 0 top
TP423  TP  [TP_40D60]  84.14 143.6 0 top
TP424  TP  [TP_40D60]  87.2 143.6 0 top
TP425  TP  [TP_40D60]  90.26 143.6 0 top
TP426  TP  [TP_40D60]  93.31 143.6 0 top
TP427  TP  [TP_40D60]  96.37 143.6 0 top
TP428  TP  [TP_40D60]  99.42 143.6 0 top
TP429  TP  [TP_40D60]  102.48 143.6 0 top
TP430  TP  [TP_40D60]  108.59 143.6 0 top
TP431  TP  [TP_40D60]  111.64 143.6 0 top
TP432  TP  [TP_40D60]  1.64 146.65 0 top
TP433  TP  [TP_40D60]  4.7 146.65 0 top
TP434  TP  [TP_40D60]  7.75 146.65 0 top
TP435  TP  [TP_40D60]  10.81 146.65 0 top
TP436  TP  [TP_40D60]  13.86 146.65 0 top
TP437  TP  [TP_40D60]  16.92 146.65 0 top
TP438  TP  [TP_40D60]  19.98 146.65 0 top
TP439  TP  [TP_40D60]  23.03 146.65 0 top
TP440  TP  [TP_40D60]  29.14 146.65 0 top
TP441  TP  [TP_40D60]  32.2 146.65 0 top
TP442  TP  [TP_40D60]  35.25 146.65 0 top
TP443  TP  [TP_40D60]  38.31 146.65 0 top
TP444  TP  [TP_40D60]  41.37 146.65 0 top
TP445  TP  [TP_40D60]  44.42 146.65 0 top
TP446  TP  [TP_40D60]  47.48 146.65 0 top
TP447  TP  [TP_40D60]  50.53 146.65 0 top
TP448  TP  [TP_40D60]  53.59 146.65 0 top
TP449  TP  [TP_40D60]  56.64 146.65 0 top
TP450  TP  [TP_40D60]  62.75 146.65 0 top
TP451  TP  [TP_40D60]  65.81 146.65 0 top
TP452  TP  [TP_40D60]  68.87 146.65 0 top
TP453  TP  [TP_40D60]  71.92 146.65 0 top
TP454  TP  [TP_40D60]  74.98 146.65 0 top
TP455  TP  [TP_40D60]  78.03 146.65 0 top
TP456  TP  [TP_40D60]  81.09 146.65 0 top
TP457  TP  [TP_40D60]  84.14 146.65 0 top
TP458  TP  [TP_40D60]  87.2 146.65 0 top
TP459  TP  [TP_40D60]  90.26 146.65 0 top
TP460  TP  [TP_40D60]  96.37 146.65 0 top
TP461  TP  [TP_40D60]  99.42 146.65 0 top
TP462  TP  [TP_40D60]  102.48 146.65 0 top
TP463  TP  [TP_40D60]  105.53 146.65 0 top
TP464  TP  [TP_40D60]  108.59 146.65 0 top
TP465  TP  [TP_40D60]  111.64 146.65 0 top
TP466  TP  [TP_40D60]  1.64 158.87 0 top
TP467  TP  [TP_40D60]  4.7 158.87 0 top
TP468  TP  [TP_40D60]  7.75 149.71 0 top
TP469  TP  [TP_40D60]  10.81 149.71 0 top
TP470  TP  [TP_40D60]  16.92 149.71 0 top
TP471  TP  [TP_40D60]  19.98 149.71 0 top
TP472  TP  [TP_40D60]  23.03 149.71 0 top
TP473  TP  [TP_40D60]  26.09 149.71 0 top
TP474  TP  [TP_40D60]  29.14 149.71 0 top
TP475  TP  [TP_40D60]  32.2 149.71 0 top
TP476  TP  [TP_40D60]  35.25 149.71 0 top
TP477  TP  [TP_40D60]  38.31 149.71 0 top
TP478  TP  [TP_40D60]  41.37 149.71 0 top
TP479  TP  [TP_40D60]  44.42 149.71 0 top
TP482  TP  [TP_40D60]  56.64 149.71 0 top
TP483  TP  [TP_40D60]  59.7 149.71 0 top
TP484  TP  [TP_40D60]  62.75 149.71 0 top
TP485  TP  [TP_40D60]  65.81 149.71 0 top
TP486  TP  [TP_40D60]  68.87 149.71 0 top
TP487  TP  [TP_40D60]  71.92 149.71 0 top
TP488  TP  [TP_40D60]  74.98 149.71 0 top
TP489  TP  [TP_40D60]  78.03 149.71 0 top
U1  -  [FC784]  54.81 59.23 0 top

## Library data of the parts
TP1-TP479 TP482-TP489 = T POINT A
U1 = FC784

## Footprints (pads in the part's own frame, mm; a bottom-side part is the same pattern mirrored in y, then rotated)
FC784
  round 0.508 smd: A1(-13.5,13.5) A2(-12.5,13.5) A3(-11.5,13.5) A4(-10.5,13.5) A5(-9.5,13.5) A6(-8.5,13.5) A7(-7.5,13.5) A8(-6.5,13.5) A9(-5.5,13.5) A10(-4.5,13.5) A11(-3.5,13.5) A12(-2.5,13.5) A13(-1.5,13.5) A14(-0.5,13.5) A15(0.5,13.5) A16(1.5,13.5) A17(2.5,13.5) A18(3.5,13.5) A19(4.5,13.5) A20(5.5,13.5) A21(6.5,13.5) A22(7.5,13.5) A23(8.5,13.5) A24(9.5,13.5) A25(10.5,13.5) A26(11.5,13.5) A27(12.5,13.5) A28(13.5,13.5) AA1(-13.5,-6.5) AA2(-12.5,-6.5) AA3(-11.5,-6.5) AA4(-10.5,-6.5) AA5(-9.5,-6.5) AA6(-8.5,-6.5) AA7(-7.5,-6.5) AA8(-6.5,-6.5) AA9(-5.5,-6.5) AA10(-4.5,-6.5) AA11(-3.5,-6.5) AA12(-2.5,-6.5) AA13(-1.5,-6.5) AA14(-0.5,-6.5) AA15(0.5,-6.5) AA16(1.5,-6.5) AA17(2.5,-6.5) AA18(3.5,-6.5) AA19(4.5,-6.5) AA20(5.5,-6.5) AA21(6.5,-6.5) AA22(7.5,-6.5) AA23(8.5,-6.5) AA24(9.5,-6.5) AA25(10.5,-6.5) AA26(11.5,-6.5) AA27(12.5,-6.5) AA28(13.5,-6.5) AB1(-13.5,-7.5) AB2(-12.5,-7.5) AB3(-11.5,-7.5) AB4(-10.5,-7.5) AB5(-9.5,-7.5) AB6(-8.5,-7.5) AB7(-7.5,-7.5) AB8(-6.5,-7.5) AB9(-5.5,-7.5) AB10(-4.5,-7.5) AB11(-3.5,-7.5) AB12(-2.5,-7.5) AB13(-1.5,-7.5) AB14(-0.5,-7.5) AB15(0.5,-7.5) AB16(1.5,-7.5) AB17(2.5,-7.5) AB18(3.5,-7.5) AB19(4.5,-7.5) AB20(5.5,-7.5) AB21(6.5,-7.5) AB22(7.5,-7.5) AB23(8.5,-7.5) AB24(9.5,-7.5) AB25(10.5,-7.5) AB26(11.5,-7.5) AB27(12.5,-7.5) AB28(13.5,-7.5) AC1(-13.5,-8.5) AC2(-12.5,-8.5) AC3(-11.5,-8.5) AC4(-10.5,-8.5) AC5(-9.5,-8.5) AC6(-8.5,-8.5) AC7(-7.5,-8.5) AC8(-6.5,-8.5) AC9(-5.5,-8.5) AC10(-4.5,-8.5) AC11(-3.5,-8.5) AC12(-2.5,-8.5) AC13(-1.5,-8.5) AC14(-0.5,-8.5) AC15(0.5,-8.5) AC16(1.5,-8.5) AC17(2.5,-8.5) AC18(3.5,-8.5) AC19(4.5,-8.5) AC20(5.5,-8.5) AC21(6.5,-8.5) AC22(7.5,-8.5) AC23(8.5,-8.5) AC24(9.5,-8.5) AC25(10.5,-8.5) AC26(11.5,-8.5) AC27(12.5,-8.5) AC28(13.5,-8.5) AD1(-13.5,-9.5) AD2(-12.5,-9.5) AD3(-11.5,-9.5) AD4(-10.5,-9.5) AD5(-9.5,-9.5) AD6(-8.5,-9.5) AD7(-7.5,-9.5) AD8(-6.5,-9.5) AD9(-5.5,-9.5) AD10(-4.5,-9.5) AD11(-3.5,-9.5) AD12(-2.5,-9.5) AD13(-1.5,-9.5) AD14(-0.5,-9.5) AD15(0.5,-9.5) AD16(1.5,-9.5) AD17(2.5,-9.5) AD18(3.5,-9.5) AD19(4.5,-9.5) AD20(5.5,-9.5) AD21(6.5,-9.5) AD22(7.5,-9.5) AD23(8.5,-9.5) AD24(9.5,-9.5) AD25(10.5,-9.5) AD26(11.5,-9.5) AD27(12.5,-9.5) AD28(13.5,-9.5) AE1(-13.5,-10.5) AE2(-12.5,-10.5) AE3(-11.5,-10.5) AE4(-10.5,-10.5) AE5(-9.5,-10.5) AE6(-8.5,-10.5) AE7(-7.5,-10.5) AE8(-6.5,-10.5) AE9(-5.5,-10.5) AE10(-4.5,-10.5) AE11(-3.5,-10.5) AE12(-2.5,-10.5) AE13(-1.5,-10.5) AE14(-0.5,-10.5) AE15(0.5,-10.5) AE16(1.5,-10.5) AE17(2.5,-10.5) AE18(3.5,-10.5) AE19(4.5,-10.5) AE20(5.5,-10.5) AE21(6.5,-10.5) AE22(7.5,-10.5) AE23(8.5,-10.5) AE24(9.5,-10.5) AE25(10.5,-10.5) AE26(11.5,-10.5) AE27(12.5,-10.5) AE28(13.5,-10.5) AF1(-13.5,-11.5) AF2(-12.5,-11.5) AF3(-11.5,-11.5) AF4(-10.5,-11.5) AF5(-9.5,-11.5) AF6(-8.5,-11.5) AF7(-7.5,-11.5) AF8(-6.5,-11.5) AF9(-5.5,-11.5) AF10(-4.5,-11.5) AF11(-3.5,-11.5) AF12(-2.5,-11.5) AF13(-1.5,-11.5) AF14(-0.5,-11.5) AF15(0.5,-11.5) AF16(1.5,-11.5) AF17(2.5,-11.5) AF18(3.5,-11.5) AF19(4.5,-11.5) AF20(5.5,-11.5) AF21(6.5,-11.5) AF22(7.5,-11.5) AF23(8.5,-11.5) AF24(9.5,-11.5) AF25(10.5,-11.5) AF26(11.5,-11.5) AF27(12.5,-11.5) AF28(13.5,-11.5) AG1(-13.5,-12.5) AG2(-12.5,-12.5) AG3(-11.5,-12.5) AG4(-10.5,-12.5) AG5(-9.5,-12.5) AG6(-8.5,-12.5) AG7(-7.5,-12.5) AG8(-6.5,-12.5) AG9(-5.5,-12.5) AG10(-4.5,-12.5) AG11(-3.5,-12.5) AG12(-2.5,-12.5) AG13(-1.5,-12.5) AG14(-0.5,-12.5) AG15(0.5,-12.5) AG16(1.5,-12.5) AG17(2.5,-12.5) AG18(3.5,-12.5) AG19(4.5,-12.5) AG20(5.5,-12.5) AG21(6.5,-12.5) AG22(7.5,-12.5) AG23(8.5,-12.5) AG24(9.5,-12.5) AG25(10.5,-12.5) AG26(11.5,-12.5) AG27(12.5,-12.5) AG28(13.5,-12.5) AH1(-13.5,-13.5) AH2(-12.5,-13.5) AH3(-11.5,-13.5) AH4(-10.5,-13.5) AH5(-9.5,-13.5) AH6(-8.5,-13.5) AH7(-7.5,-13.5) AH8(-6.5,-13.5) AH9(-5.5,-13.5) AH10(-4.5,-13.5) AH11(-3.5,-13.5) AH12(-2.5,-13.5) AH13(-1.5,-13.5) AH14(-0.5,-13.5) AH15(0.5,-13.5) AH16(1.5,-13.5) AH17(2.5,-13.5) AH18(3.5,-13.5) AH19(4.5,-13.5) AH20(5.5,-13.5) AH21(6.5,-13.5) AH22(7.5,-13.5) AH23(8.5,-13.5) AH24(9.5,-13.5) AH25(10.5,-13.5) AH26(11.5,-13.5) AH27(12.5,-13.5) AH28(13.5,-13.5) B1(-13.5,12.5) B2(-12.5,12.5) B3(-11.5,12.5) B4(-10.5,12.5) B5(-9.5,12.5) B6(-8.5,12.5) B7(-7.5,12.5) B8(-6.5,12.5) B9(-5.5,12.5) B10(-4.5,12.5) B11(-3.5,12.5) B12(-2.5,12.5) B13(-1.5,12.5) B14(-0.5,12.5) B15(0.5,12.5) B16(1.5,12.5) B17(2.5,12.5) B18(3.5,12.5) B19(4.5,12.5) B20(5.5,12.5) B21(6.5,12.5) B22(7.5,12.5) B23(8.5,12.5) B24(9.5,12.5) B25(10.5,12.5) B26(11.5,12.5) B27(12.5,12.5) B28(13.5,12.5) C1(-13.5,11.5) C2(-12.5,11.5) C3(-11.5,11.5) C4(-10.5,11.5) C5(-9.5,11.5) C6(-8.5,11.5) C7(-7.5,11.5) C8(-6.5,11.5) C9(-5.5,11.5) C10(-4.5,11.5) C11(-3.5,11.5) C12(-2.5,11.5) C13(-1.5,11.5) C14(-0.5,11.5) C15(0.5,11.5) C16(1.5,11.5) C17(2.5,11.5) C18(3.5,11.5) C19(4.5,11.5) C20(5.5,11.5) C21(6.5,11.5) C22(7.5,11.5) C23(8.5,11.5) C24(9.5,11.5) C25(10.5,11.5) C26(11.5,11.5) C27(12.5,11.5) C28(13.5,11.5) D1(-13.5,10.5) D2(-12.5,10.5) D3(-11.5,10.5) D4(-10.5,10.5) D5(-9.5,10.5) D6(-8.5,10.5) D7(-7.5,10.5) D8(-6.5,10.5) D9(-5.5,10.5) D10(-4.5,10.5) D11(-3.5,10.5) D12(-2.5,10.5) D13(-1.5,10.5) D14(-0.5,10.5) D15(0.5,10.5) D16(1.5,10.5) D17(2.5,10.5) D18(3.5,10.5) D19(4.5,10.5) D20(5.5,10.5) D21(6.5,10.5) D22(7.5,10.5) D23(8.5,10.5) D24(9.5,10.5) D25(10.5,10.5) D26(11.5,10.5) D27(12.5,10.5) D28(13.5,10.5) E1(-13.5,9.5) E2(-12.5,9.5) E3(-11.5,9.5) E4(-10.5,9.5) E5(-9.5,9.5) E6(-8.5,9.5) E7(-7.5,9.5) E8(-6.5,9.5) E9(-5.5,9.5) E10(-4.5,9.5) E11(-3.5,9.5) E12(-2.5,9.5) E13(-1.5,9.5) E14(-0.5,9.5) E15(0.5,9.5) E16(1.5,9.5) E17(2.5,9.5) E18(3.5,9.5) E19(4.5,9.5) E20(5.5,9.5) E21(6.5,9.5) E22(7.5,9.5) E23(8.5,9.5) E24(9.5,9.5) E25(10.5,9.5) E26(11.5,9.5) E27(12.5,9.5) E28(13.5,9.5) F1(-13.5,8.5) F2(-12.5,8.5) F3(-11.5,8.5) F4(-10.5,8.5) F5(-9.5,8.5) F6(-8.5,8.5) F7(-7.5,8.5) F8(-6.5,8.5) F9(-5.5,8.5) F10(-4.5,8.5) F11(-3.5,8.5) F12(-2.5,8.5) F13(-1.5,8.5) F14(-0.5,8.5) F15(0.5,8.5) F16(1.5,8.5) F17(2.5,8.5) F18(3.5,8.5) F19(4.5,8.5) F20(5.5,8.5) F21(6.5,8.5) F22(7.5,8.5) F23(8.5,8.5) F24(9.5,8.5) F25(10.5,8.5) F26(11.5,8.5) F27(12.5,8.5) F28(13.5,8.5) G1(-13.5,7.5) G2(-12.5,7.5) G3(-11.5,7.5) G4(-10.5,7.5) G5(-9.5,7.5) G6(-8.5,7.5) G7(-7.5,7.5) G8(-6.5,7.5) G9(-5.5,7.5) G10(-4.5,7.5) G11(-3.5,7.5) G12(-2.5,7.5) G13(-1.5,7.5) G14(-0.5,7.5) G15(0.5,7.5) G16(1.5,7.5) G17(2.5,7.5) G18(3.5,7.5) G19(4.5,7.5) G20(5.5,7.5) G21(6.5,7.5) G22(7.5,7.5) G23(8.5,7.5) G24(9.5,7.5) G25(10.5,7.5) G26(11.5,7.5) G27(12.5,7.5) G28(13.5,7.5) H1(-13.5,6.5) H2(-12.5,6.5) H3(-11.5,6.5) H4(-10.5,6.5) H5(-9.5,6.5) H6(-8.5,6.5) H7(-7.5,6.5) H8(-6.5,6.5) H9(-5.5,6.5) H10(-4.5,6.5) H11(-3.5,6.5) H12(-2.5,6.5) H13(-1.5,6.5) H14(-0.5,6.5) H15(0.5,6.5) H16(1.5,6.5) H17(2.5,6.5) H18(3.5,6.5) H19(4.5,6.5) H20(5.5,6.5) H21(6.5,6.5) H22(7.5,6.5) H23(8.5,6.5) H24(9.5,6.5) H25(10.5,6.5) H26(11.5,6.5) H27(12.5,6.5) H28(13.5,6.5) J1(-13.5,5.5) J2(-12.5,5.5) J3(-11.5,5.5) J4(-10.5,5.5) J5(-9.5,5.5) J6(-8.5,5.5) J7(-7.5,5.5) J8(-6.5,5.5) J9(-5.5,5.5) J10(-4.5,5.5) J11(-3.5,5.5) J12(-2.5,5.5) J13(-1.5,5.5) J14(-0.5,5.5) J15(0.5,5.5) J16(1.5,5.5) J17(2.5,5.5) J18(3.5,5.5) J19(4.5,5.5) J20(5.5,5.5) J21(6.5,5.5) J22(7.5,5.5) J23(8.5,5.5) J24(9.5,5.5) J25(10.5,5.5) J26(11.5,5.5) J27(12.5,5.5) J28(13.5,5.5) K1(-13.5,4.5) K2(-12.5,4.5) K3(-11.5,4.5) K4(-10.5,4.5) K5(-9.5,4.5) K6(-8.5,4.5) K7(-7.5,4.5) K8(-6.5,4.5) K9(-5.5,4.5) K10(-4.5,4.5) K11(-3.5,4.5) K12(-2.5,4.5) K13(-1.5,4.5) K14(-0.5,4.5) K15(0.5,4.5) K16(1.5,4.5) K17(2.5,4.5) K18(3.5,4.5) K19(4.5,4.5) K20(5.5,4.5) K21(6.5,4.5) K22(7.5,4.5) K23(8.5,4.5) K24(9.5,4.5) K25(10.5,4.5) K26(11.5,4.5) K27(12.5,4.5) K28(13.5,4.5) L1(-13.5,3.5) L2(-12.5,3.5) L3(-11.5,3.5) L4(-10.5,3.5) L5(-9.5,3.5) L6(-8.5,3.5) L7(-7.5,3.5) L8(-6.5,3.5) L9(-5.5,3.5) L10(-4.5,3.5) L11(-3.5,3.5) L12(-2.5,3.5) L13(-1.5,3.5) L14(-0.5,3.5) L15(0.5,3.5) L16(1.5,3.5) L17(2.5,3.5) L18(3.5,3.5) L19(4.5,3.5) L20(5.5,3.5) L21(6.5,3.5) L22(7.5,3.5) L23(8.5,3.5) L24(9.5,3.5) L25(10.5,3.5) L26(11.5,3.5) L27(12.5,3.5) L28(13.5,3.5) M1(-13.5,2.5) M2(-12.5,2.5) M3(-11.5,2.5) M4(-10.5,2.5) M5(-9.5,2.5) M6(-8.5,2.5) M7(-7.5,2.5) M8(-6.5,2.5) M9(-5.5,2.5) M10(-4.5,2.5) M11(-3.5,2.5) M12(-2.5,2.5) M13(-1.5,2.5) M14(-0.5,2.5) M15(0.5,2.5) M16(1.5,2.5) M17(2.5,2.5) M18(3.5,2.5) M19(4.5,2.5) M20(5.5,2.5) M21(6.5,2.5) M22(7.5,2.5) M23(8.5,2.5) M24(9.5,2.5) M25(10.5,2.5) M26(11.5,2.5) M27(12.5,2.5) M28(13.5,2.5) N1(-13.5,1.5) N2(-12.5,1.5) N3(-11.5,1.5) N4(-10.5,1.5) N5(-9.5,1.5) N6(-8.5,1.5) N7(-7.5,1.5) N8(-6.5,1.5) N9(-5.5,1.5) N10(-4.5,1.5) N11(-3.5,1.5) N12(-2.5,1.5) N13(-1.5,1.5) N14(-0.5,1.5) N15(0.5,1.5) N16(1.5,1.5) N17(2.5,1.5) N18(3.5,1.5) N19(4.5,1.5) N20(5.5,1.5) N21(6.5,1.5) N22(7.5,1.5) N23(8.5,1.5) N24(9.5,1.5) N25(10.5,1.5) N26(11.5,1.5) N27(12.5,1.5) N28(13.5,1.5) P1(-13.5,0.5) P2(-12.5,0.5) P3(-11.5,0.5) P4(-10.5,0.5) P5(-9.5,0.5) P6(-8.5,0.5) P7(-7.5,0.5) P8(-6.5,0.5) P9(-5.5,0.5) P10(-4.5,0.5) P11(-3.5,0.5) P12(-2.5,0.5) P13(-1.5,0.5) P14(-0.5,0.5) P15(0.5,0.5) P16(1.5,0.5) P17(2.5,0.5) P18(3.5,0.5) P19(4.5,0.5) P20(5.5,0.5) P21(6.5,0.5) P22(7.5,0.5) P23(8.5,0.5) P24(9.5,0.5) P25(10.5,0.5) P26(11.5,0.5) P27(12.5,0.5) P28(13.5,0.5) R1(-13.5,-0.5) R2(-12.5,-0.5) R3(-11.5,-0.5) R4(-10.5,-0.5) R5(-9.5,-0.5) R6(-8.5,-0.5) R7(-7.5,-0.5) R8(-6.5,-0.5) R9(-5.5,-0.5) R10(-4.5,-0.5) R11(-3.5,-0.5) R12(-2.5,-0.5) R13(-1.5,-0.5) R14(-0.5,-0.5) R15(0.5,-0.5) R16(1.5,-0.5) R17(2.5,-0.5) R18(3.5,-0.5) R19(4.5,-0.5) R20(5.5,-0.5) R21(6.5,-0.5) R22(7.5,-0.5) R23(8.5,-0.5) R24(9.5,-0.5) R25(10.5,-0.5) R26(11.5,-0.5) R27(12.5,-0.5) R28(13.5,-0.5) T1(-13.5,-1.5) T2(-12.5,-1.5) T3(-11.5,-1.5) T4(-10.5,-1.5) T5(-9.5,-1.5) T6(-8.5,-1.5) T7(-7.5,-1.5) T8(-6.5,-1.5) T9(-5.5,-1.5) T10(-4.5,-1.5) T11(-3.5,-1.5) T12(-2.5,-1.5) T13(-1.5,-1.5) T14(-0.5,-1.5) T15(0.5,-1.5) T16(1.5,-1.5) T17(2.5,-1.5) T18(3.5,-1.5) T19(4.5,-1.5) T20(5.5,-1.5) T21(6.5,-1.5) T22(7.5,-1.5) T23(8.5,-1.5) T24(9.5,-1.5) T25(10.5,-1.5) T26(11.5,-1.5) T27(12.5,-1.5) T28(13.5,-1.5) U1(-13.5,-2.5) U2(-12.5,-2.5) U3(-11.5,-2.5) U4(-10.5,-2.5) U5(-9.5,-2.5) U6(-8.5,-2.5) U7(-7.5,-2.5) U8(-6.5,-2.5) U9(-5.5,-2.5) U10(-4.5,-2.5) U11(-3.5,-2.5) U12(-2.5,-2.5) U13(-1.5,-2.5) U14(-0.5,-2.5) U15(0.5,-2.5) U16(1.5,-2.5) U17(2.5,-2.5) U18(3.5,-2.5) U19(4.5,-2.5) U20(5.5,-2.5) U21(6.5,-2.5) U22(7.5,-2.5) U23(8.5,-2.5) U24(9.5,-2.5) U25(10.5,-2.5) U26(11.5,-2.5) U27(12.5,-2.5) U28(13.5,-2.5) V1(-13.5,-3.5) V2(-12.5,-3.5) V3(-11.5,-3.5) V4(-10.5,-3.5) V5(-9.5,-3.5) V6(-8.5,-3.5) V7(-7.5,-3.5) V8(-6.5,-3.5) V9(-5.5,-3.5) V10(-4.5,-3.5) V11(-3.5,-3.5) V12(-2.5,-3.5) V13(-1.5,-3.5) V14(-0.5,-3.5) V15(0.5,-3.5) V16(1.5,-3.5) V17(2.5,-3.5) V18(3.5,-3.5) V19(4.5,-3.5) V20(5.5,-3.5) V21(6.5,-3.5) V22(7.5,-3.5) V23(8.5,-3.5) V24(9.5,-3.5) V25(10.5,-3.5) V26(11.5,-3.5) V27(12.5,-3.5) V28(13.5,-3.5) W1(-13.5,-4.5) W2(-12.5,-4.5) W3(-11.5,-4.5) W4(-10.5,-4.5) W5(-9.5,-4.5) W6(-8.5,-4.5) W7(-7.5,-4.5) W8(-6.5,-4.5) W9(-5.5,-4.5) W10(-4.5,-4.5) W11(-3.5,-4.5) W12(-2.5,-4.5) W13(-1.5,-4.5) W14(-0.5,-4.5) W15(0.5,-4.5) W16(1.5,-4.5) W17(2.5,-4.5) W18(3.5,-4.5) W19(4.5,-4.5) W20(5.5,-4.5) W21(6.5,-4.5) W22(7.5,-4.5) W23(8.5,-4.5) W24(9.5,-4.5) W25(10.5,-4.5) W26(11.5,-4.5) W27(12.5,-4.5) W28(13.5,-4.5) Y1(-13.5,-5.5) Y2(-12.5,-5.5) Y3(-11.5,-5.5) Y4(-10.5,-5.5) Y5(-9.5,-5.5) Y6(-8.5,-5.5) Y7(-7.5,-5.5) Y8(-6.5,-5.5) Y9(-5.5,-5.5) Y10(-4.5,-5.5) Y11(-3.5,-5.5) Y12(-2.5,-5.5) Y13(-1.5,-5.5) Y14(-0.5,-5.5) Y15(0.5,-5.5) Y16(1.5,-5.5) Y17(2.5,-5.5) Y18(3.5,-5.5) Y19(4.5,-5.5) Y20(5.5,-5.5) Y21(6.5,-5.5) Y22(7.5,-5.5) Y23(8.5,-5.5) Y24(9.5,-5.5) Y25(10.5,-5.5) Y26(11.5,-5.5) Y27(12.5,-5.5) Y28(13.5,-5.5)
TP_40D60
  round 1.524 hole 1.016: 1(0,0)
unnamed
  round 6.096 hole 3.175 unplated: (0,0)

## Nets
GND: U1.A6(VSS1) U1.A16(VSS2) U1.A22(VSSA1) U1.A25(VSSA2) U1.A26(VSSA3) U1.AA6(VSS71) U1.AA16(VSS72) U1.AA22(VSSA58) U1.AA25(VSSA59) U1.AB3(VSS73) U1.AB13(VSS74) U1.AB22(VSSA60) U1.AB24(VSSA61) U1.AB27(VSSA62) U1.AB28(VSSA63) U1.AC10(VSS75) U1.AC20(VSS76) U1.AC22(VSSA64) U1.AC25(VSSA65) U1.AD7(VSS77) U1.AD17(VSS78) U1.AD22(VSSA66) U1.AD24(VSSA67) U1.AD27(VSSA68) U1.AD28(VSSA69) U1.AE4(VSS79) U1.AE14(VSS80) U1.AE22(VSSA70) U1.AE25(VSSA71) U1.AF11(VSS81) U1.AF21(VSS82) U1.AF22(VSSA72) U1.AF24(VSSA73) U1.AF27(VSSA74) U1.AF28(VSSA75) U1.AG8(VSS83) U1.AG18(VSS84) U1.AG23(VSS85) U1.AG24(VSSA76) U1.AG25(VSSA77) U1.AH1(VSS86) U1.AH5(VSS87) U1.AH15(VSS88) U1.AH24(VSSA78) U1.AH27(VSSA79) U1.AH28(VSSA80) U1.B3(VSS3) U1.B13(VSS4) U1.B22(VSSA6) U1.B24(VSSA7) U1.B27(VSSA8) U1.B28(VSSA9) U1.C10(VSS5) U1.C20(VSS6) U1.C22(VSSA10) U1.C25(VSSA11) U1.D7(VSS7) U1.D17(VSS8) U1.D22(VSSA12) U1.D24(VSSA13) U1.D27(VSSA14) U1.D28(VSSA15) U1.E4(VSS9) U1.E14(VSS10) U1.E22(VSSA16) U1.E23(VSSA4) U1.E24(VSSA5) U1.E25(VSSA17) U1.F1(VSS11) U1.F11(VSS12) U1.F24(VSSA18) U1.F27(VSSA19) U1.F28(VSSA20) U1.G8(VSS13) U1.G18(VSS14) U1.G22(VSSA21) U1.G25(VSSA22) U1.H5(VSS15) U1.H15(VSS16) U1.H24(VSSA23) U1.H27(VSSA24) U1.H28(VSSA25) U1.J2(VSS17) U1.J22(VSSA26) U1.J25(VSSA27) U1.K9(VSS18) U1.K14(VSS19) U1.K20(VSS20) U1.K21(VSSA28) U1.K22(VSSA29) U1.K24(VSSA30) U1.K27(VSSA31) U1.K28(VSSA32) U1.L6(VSS21) U1.L11(VSS22) U1.L13(VSS23) U1.L15(VSS24) U1.L17(VSS25) U1.L19(VSS26) U1.L25(VSSA33) U1.M3(VSS27) U1.M12(VSS28) U1.M14(VSS29) U1.M16(VSS30) U1.M18(VSS31) U1.M20(VSS32) U1.M24(VSSA34) U1.M27(VSSA35) U1.M28(VSSA36) U1.N11(VSS33) U1.N13(VSS34) U1.N15(VSS35) U1.N17(VSS36) U1.N19(VSS37) U1.N22(VSSA37) U1.N25(VSSA38) U1.P7(VSS38) U1.P12(VSS39) U1.P14(VSS40) U1.P16(VSS41) U1.P18(VSS42) U1.P20(VSS43) U1.P27(VSSA39) U1.P28(VSSA40) U1.R4(VSS44) U1.R11(VSS45) U1.R13(VSS46) U1.R15(VSS47) U1.R17(VSS48) U1.R19(VSS49) U1.R22(VSSA41) U1.R25(VSSA42) U1.T1(VSS50) U1.T12(VSS51) U1.T14(VSS52) U1.T16(VSS53) U1.T18(VSS54) U1.T20(VSS55) U1.T24(VSSA43) U1.T27(VSSA44) U1.T28(VSSA45) U1.U8(VSS56) U1.U11(VSS57) U1.U13(VSS58) U1.U15(VSS59) U1.U17(VSS60) U1.U19(VSS61) U1.U25(VSSA46) U1.V5(VSS62) U1.V12(VSS63) U1.V14(VSS64) U1.V16(VSS65) U1.V18(VSS66) U1.V20(VSS67) U1.V21(VSSA47) U1.V22(VSSA48) U1.V24(VSSA49) U1.V27(VSSA50) U1.V28(VSSA51) U1.W2(VSS68) U1.W22(VSSA52) U1.W25(VSSA53) U1.Y9(VSS69) U1.Y19(VSS70) U1.Y22(VSSA54) U1.Y24(VSSA55) U1.Y27(VSSA56) U1.Y28(VSSA57)
VDD: U1.M15(VDD1) U1.M17(VDD2) U1.M19(VDD3) U1.N14(VDD4) U1.N16(VDD5) U1.N18(VDD6) U1.N20(VDD7) U1.P13(VDD8) U1.P15(VDD9) U1.P17(VDD10) U1.P19(VDD11) U1.R14(VDD12) U1.R18(VDD13) U1.R20(VDD14) U1.T13(VDD15) U1.T15(VDD16) U1.T17(VDD17) U1.T19(VDD18) U1.U14(VDD19) U1.U16(VDD20) U1.U18(VDD21)
VDD18: U1.V13(VDD18_1) U1.V15(VDD18_2) U1.V17(VDD18_3) U1.V19(VDD18_4) U1.W11(VDD18_5) U1.W21(VDD18_6)
VDD25: U1.L20(VDD25_1) U1.M13(VDD25_2) U1.R16(VDD25_3) U1.U12(VDD25_4) U1.U20(VDD25_5)
VDDA: U1.AA26(VDDA_18) U1.AB23(VDDA_19) U1.AC26(VDDA_20) U1.AD23(VDDA_21) U1.AE26(VDDA_22) U1.AF23(VDDA_23) U1.AG26(VDDA_24) U1.B23(VDDA_1) U1.C26(VDDA_2) U1.D23(VDDA_3) U1.E26(VDDA_4) U1.F23(VDDA_5) U1.G26(VDDA_6) U1.H23(VDDA_7) U1.J26(VDDA_8) U1.L26(VDDA_9) U1.M23(VDDA_10) U1.N26(VDDA_11) U1.P24(VDDA_12) U1.R26(VDDA_13) U1.T23(VDDA_14) U1.U26(VDDA_15) U1.W26(VDDA_16) U1.Y23(VDDA_17)
VDDA25: U1.L22(VDDA25_1) U1.N21(VDDA25_2) U1.R21(VDDA25_3) U1.U22(VDDA25_4)
VDDAUX2: U1.K11(VDDAUX2_1) U1.K15(VDDAUX2_2) U1.L14(VDDAUX2_3) U1.L16(VDDAUX2_4) U1.L18(VDDAUX2_5)
VDDAUX4: U1.P11(VDDAUX4_1) U1.R12(VDDAUX4_2) U1.T11(VDDAUX4_3) U1.V11(VDDAUX4_4)
VDDAUX5: U1.L12(VDDAUX5_1) U1.M11(VDDAUX5_2) U1.N12(VDDAUX5_3)
VDDI0: U1.AA1(VDDI0_1) U1.AA11(VDDI0_2) U1.AB8(VDDI0_3) U1.AC5(VDDI0_4) U1.AD2(VDDI0_5) U1.AE9(VDDI0_6) U1.AF6(VDDI0_7) U1.AG3(VDDI0_8) U1.AH10(VDDI0_9)
VDDI1: U1.AA21(VDDI1_2) U1.AB18(VDDI1_3) U1.AC15(VDDI1_4) U1.AE19(VDDI1_5) U1.AF16(VDDI1_6) U1.AH20(VDDI1_7) U1.W17(VDDI1_1)
VDDI2: U1.A11(VDDI2_1) U1.A21(VDDI2_2) U1.B8(VDDI2_3) U1.B18(VDDI2_4) U1.C15(VDDI2_5) U1.D12(VDDI2_6) U1.E9(VDDI2_7) U1.E19(VDDI2_8) U1.F16(VDDI2_9) U1.G13(VDDI2_10) U1.H20(VDDI2_11) U1.J17(VDDI2_12)
VDDI3: U1.H10(VDDI3_1) U1.K13(VDDI3_2)
VDDI4: U1.K4(VDDI4_1) U1.L1(VDDI4_2) U1.M8(VDDI4_3) U1.N5(VDDI4_4) U1.P2(VDDI4_5) U1.R9(VDDI4_6) U1.T6(VDDI4_7) U1.U3(VDDI4_8) U1.U10(VDDI4_9) U1.W7(VDDI4_10) U1.Y4(VDDI4_11)
VDDI5: U1.A1(VDDI5_1) U1.C5(VDDI5_2) U1.D2(VDDI5_3) U1.F6(VDDI5_4) U1.G3(VDDI5_5) U1.J7(VDDI5_6)
VDDI7: U1.AD12(VDDI7_2) U1.AG13(VDDI7_3) U1.Y14(VDDI7_1)
VDDSREF: U1.K23(VDDSREF_1) U1.L21(VDDSREF_2) U1.P23(VDDSREF_3) U1.U21(VDDSREF_4) U1.V23(VDDSREF_5)
IO1: TP1.1(TP) U1.A2(IO1)
IO2: TP2.1(TP) U1.A3(IO2)
IO3: TP3.1(TP) U1.A4(IO3)
IO4: TP4.1(TP) U1.A5(IO4)
IO5: TP5.1(TP) U1.A7(IO5)
IO6: TP6.1(TP) U1.A8(IO6)
IO7: TP7.1(TP) U1.A9(IO7)
IO8: TP8.1(TP) U1.A10(IO8)
IO9: TP9.1(TP) U1.A12(IO9)
IO10: TP10.1(TP) U1.A13(IO10)
IO11: TP11.1(TP) U1.A14(IO11)
IO12: TP12.1(TP) U1.A15(IO12)
IO13: TP13.1(TP) U1.A17(IO13)
IO14: TP14.1(TP) U1.A18(IO14)
IO15: TP15.1(TP) U1.A19(IO15)
IO16: TP16.1(TP) U1.A20(IO16)
IO17: TP17.1(TP) U1.B1(IO17)
IO18: TP18.1(TP) U1.B2(IO18)
IO19: TP19.1(TP) U1.B4(IO19)
IO20: TP20.1(TP) U1.B5(IO20)
IO21: TP21.1(TP) U1.B6(IO21)
IO22: TP22.1(TP) U1.B7(IO22)
IO23: TP23.1(TP) U1.B9(IO23)
IO24: TP24.1(TP) U1.B10(IO24)
IO25: TP25.1(TP) U1.B11(IO25)
IO26: TP26.1(TP) U1.B12(IO26)
IO27: TP27.1(TP) U1.B14(IO27)
IO28: TP28.1(TP) U1.B15(IO28)
IO29: TP29.1(TP) U1.B16(IO29)
IO30: TP30.1(TP) U1.B17(IO30)
IO31: TP31.1(TP) U1.B19(IO31)
IO32: TP32.1(TP) U1.B20(IO32)
IO33: TP33.1(TP) U1.B21(IO33)
IO34: TP34.1(TP) U1.C1(IO34)
IO35: TP35.1(TP) U1.C2(IO35)
IO36: TP36.1(TP) U1.C3(IO36)
IO37: TP37.1(TP) U1.C4(IO37)
IO38: TP38.1(TP) U1.C6(IO38)
IO39: TP39.1(TP) U1.C7(IO39)
IO40: TP40.1(TP) U1.C8(IO40)
IO41: TP41.1(TP) U1.C9(IO41)
IO42: TP42.1(TP) U1.C11(IO42)
IO43: TP43.1(TP) U1.C12(IO43)
IO44: TP44.1(TP) U1.C13(IO44)
IO45: TP45.1(TP) U1.C14(IO45)
IO46: TP46.1(TP) U1.C16(IO46)
IO47: TP47.1(TP) U1.C17(IO47)
IO48: TP48.1(TP) U1.C18(IO48)
IO49: TP49.1(TP) U1.C19(IO49)
IO50: TP50.1(TP) U1.C21(IO50)
IO51: TP51.1(TP) U1.D1(IO51)
IO52: TP52.1(TP) U1.D3(IO52)
IO53: TP53.1(TP) U1.D4(IO53)
IO54: TP54.1(TP) U1.D5(IO54)
IO55: TP55.1(TP) U1.D6(IO55)
IO56: TP56.1(TP) U1.D8(IO56)
IO57: TP57.1(TP) U1.D9(IO57)
IO58: TP58.1(TP) U1.D10(IO58)
IO59: TP59.1(TP) U1.D11(IO59)
IO60: TP60.1(TP) U1.D13(IO60)
IO61: TP61.1(TP) U1.D14(IO61)
IO62: TP62.1(TP) U1.D15(IO62)
IO63: TP63.1(TP) U1.D16(IO63)
IO64: TP64.1(TP) U1.D18(IO64)
IO65: TP65.1(TP) U1.D19(IO65)
IO66: TP66.1(TP) U1.D20(IO66)
IO67: TP67.1(TP) U1.D21(IO67)
IO68: TP68.1(TP) U1.E1(IO68)
IO69: TP69.1(TP) U1.E2(IO69)
IO70: TP70.1(TP) U1.E3(IO70)
IO71: TP71.1(TP) U1.E5(IO71)
IO72: TP72.1(TP) U1.E6(IO72)
IO73: TP73.1(TP) U1.E7(IO73)
IO74: TP74.1(TP) U1.E8(IO74)
IO75: TP75.1(TP) U1.E10(IO75)
IO76: TP76.1(TP) U1.E11(IO76)
IO77: TP77.1(TP) U1.E12(IO77)
IO78: TP78.1(TP) U1.E13(IO78)
IO79: TP79.1(TP) U1.E15(IO79)
IO80: TP80.1(TP) U1.E16(IO80)
IO81: TP81.1(TP) U1.E17(IO81)
IO82: TP82.1(TP) U1.E18(IO82)
IO83: TP83.1(TP) U1.E20(IO83)
IO84: TP84.1(TP) U1.E21(IO84)
IO85: TP85.1(TP) U1.F2(IO85)
IO86: TP86.1(TP) U1.F3(IO86)
IO87: TP87.1(TP) U1.F4(IO87)
IO88: TP88.1(TP) U1.F5(IO88)
IO89: TP89.1(TP) U1.F7(IO89)
IO90: TP90.1(TP) U1.F8(IO90)
IO91: TP91.1(TP) U1.F9(IO91)
IO92: TP92.1(TP) U1.F10(IO92)
IO93: TP93.1(TP) U1.F12(IO93)
IO94: TP94.1(TP) U1.F13(IO94)
IO95: TP95.1(TP) U1.F14(IO95)
IO96: TP96.1(TP) U1.F15(IO96)
IO97: TP97.1(TP) U1.F17(IO97)
IO98: TP98.1(TP) U1.F18(IO98)
IO99: TP99.1(TP) U1.F19(IO99)
IO100: TP100.1(TP) U1.F20(IO100)
IO101: TP101.1(TP) U1.F21(IO101)
IO102: TP102.1(TP) U1.G1(IO102)
IO103: TP103.1(TP) U1.G2(IO103)
IO104: TP104.1(TP) U1.G4(IO104)
IO105: TP105.1(TP) U1.G5(IO105)
IO106: TP106.1(TP) U1.G6(IO106)
IO107: TP107.1(TP) U1.G7(IO107)
IO108: TP108.1(TP) U1.G9(IO108)
IO109: TP109.1(TP) U1.G10(IO109)
IO110: TP110.1(TP) U1.G11(IO110)
IO111: TP111.1(TP) U1.G12(IO111)
IO112: TP112.1(TP) U1.G14(IO112)
IO113: TP113.1(TP) U1.G15(IO113)
IO114: TP114.1(TP) U1.G16(IO114)
IO115: TP115.1(TP) U1.G17(IO115)
IO116: TP116.1(TP) U1.G19(IO116)
IO117: TP117.1(TP) U1.G20(IO117)
IO118: TP118.1(TP) U1.G21(IO118)
IO119: TP119.1(TP) U1.H1(IO119)
IO120: TP120.1(TP) U1.H2(IO120)
IO121: TP121.1(TP) U1.H3(IO121)
IO122: TP122.1(TP) U1.H4(IO122)
IO123: TP123.1(TP) U1.H6(IO123)
IO124: TP124.1(TP) U1.H7(IO124)
IO125: TP125.1(TP) U1.H8(IO125)
IO126: TP126.1(TP) U1.H9(IO126)
IO127: TP127.1(TP) U1.H11(IO127)
IO128: TP128.1(TP) U1.H12(IO128)
IO129: TP129.1(TP) U1.H13(IO129)
IO130: TP130.1(TP) U1.H14(IO130)
IO131: TP131.1(TP) U1.H16(IO131)
IO132: TP132.1(TP) U1.H17(IO132)
IO133: TP133.1(TP) U1.H18(IO133)
IO134: TP134.1(TP) U1.H19(IO134)
IO135: TP135.1(TP) U1.H21(IO135)
IO136: TP136.1(TP) U1.J1(IO136)
IO137: TP137.1(TP) U1.J3(IO137)
IO138: TP138.1(TP) U1.J4(IO138)
IO139: TP139.1(TP) U1.J5(IO139)
IO140: TP140.1(TP) U1.J6(IO140)
IO141: TP141.1(TP) U1.J8(IO141)
IO142: TP142.1(TP) U1.J9(IO142)
IO143: TP143.1(TP) U1.J10(IO143)
IO144: TP144.1(TP) U1.J11(IO144)
IO145: TP145.1(TP) U1.J12(IO145)
IO146: TP146.1(TP) U1.J13(IO146)
IO147: TP147.1(TP) U1.J14(IO147)
IO148: TP148.1(TP) U1.J15(IO148)
IO149: TP149.1(TP) U1.J16(IO149)
IO150: TP150.1(TP) U1.J18(IO150)
IO151: TP151.1(TP) U1.J19(IO151)
IO152: TP152.1(TP) U1.J20(IO152)
IO153: TP153.1(TP) U1.J21(IO153)
IO154: TP154.1(TP) U1.K1(IO154)
IO155: TP155.1(TP) U1.K2(IO155)
IO156: TP156.1(TP) U1.K3(IO156)
IO157: TP157.1(TP) U1.K5(IO157)
IO158: TP158.1(TP) U1.K6(IO158)
IO159: TP159.1(TP) U1.K7(IO159)
IO160: TP160.1(TP) U1.K8(IO160)
IO161: TP161.1(TP) U1.K10(IO161)
IO162: TP162.1(TP) U1.K12(IO162)
IO163: TP163.1(TP) U1.K16(IO163)
IO164: TP164.1(TP) U1.K17(IO164)
IO165: TP165.1(TP) U1.K18(IO165)
IO166: TP166.1(TP) U1.K19(IO166)
IO167: TP167.1(TP) U1.L2(IO167)
IO168: TP168.1(TP) U1.L3(IO168)
IO169: TP169.1(TP) U1.L4(IO169)
IO170: TP170.1(TP) U1.L5(IO170)
IO171: TP171.1(TP) U1.L7(IO171)
IO172: TP172.1(TP) U1.L8(IO172)
IO173: TP173.1(TP) U1.L9(IO173)
IO174: TP174.1(TP) U1.L10(IO174)
IO175: TP175.1(TP) U1.M1(IO175)
IO176: TP176.1(TP) U1.M2(IO176)
IO177: TP177.1(TP) U1.M4(IO177)
IO178: TP178.1(TP) U1.M5(IO178)
IO179: TP179.1(TP) U1.M6(IO179)
IO180: TP180.1(TP) U1.M7(IO180)
IO181: TP181.1(TP) U1.M9(IO181)
IO182: TP182.1(TP) U1.M10(IO182)
IO183: TP183.1(TP) U1.N1(IO183)
IO184: TP184.1(TP) U1.N2(IO184)
IO185: TP185.1(TP) U1.N3(IO185)
IO186: TP186.1(TP) U1.N4(IO186)
IO187: TP187.1(TP) U1.N6(IO187)
IO188: TP188.1(TP) U1.N7(IO188)
IO189: TP189.1(TP) U1.N8(IO189)
IO190: TP190.1(TP) U1.N9(IO190)
IO191: TP191.1(TP) U1.N10(IO191)
IO192: TP192.1(TP) U1.P1(IO192)
IO193: TP193.1(TP) U1.P3(IO193)
IO194: TP194.1(TP) U1.P4(IO194)
IO195: TP195.1(TP) U1.P5(IO195)
IO196: TP196.1(TP) U1.P6(IO196)
IO197: TP197.1(TP) U1.P8(IO197)
IO198: TP198.1(TP) U1.P9(IO198)
IO199: TP199.1(TP) U1.P10(IO199)
IO200: TP200.1(TP) U1.R1(IO200)
IO201: TP201.1(TP) U1.R2(IO201)
IO202: TP202.1(TP) U1.R3(IO202)
IO203: TP203.1(TP) U1.R5(IO203)
IO204: TP204.1(TP) U1.R6(IO204)
IO205: TP205.1(TP) U1.R7(IO205)
IO206: TP206.1(TP) U1.R8(IO206)
IO207: TP207.1(TP) U1.R10(IO207)
IO208: TP208.1(TP) U1.T2(IO208)
IO209: TP209.1(TP) U1.T3(IO209)
IO210: TP210.1(TP) U1.T4(IO210)
IO211: TP211.1(TP) U1.T5(IO211)
IO212: TP212.1(TP) U1.T7(IO212)
IO213: TP213.1(TP) U1.T8(IO213)
IO214: TP214.1(TP) U1.T9(IO214)
IO215: TP215.1(TP) U1.T10(IO215)
IO216: TP216.1(TP) U1.U1(IO216)
IO217: TP217.1(TP) U1.U2(IO217)
IO218: TP218.1(TP) U1.U4(IO218)
IO219: TP219.1(TP) U1.U5(IO219)
IO220: TP220.1(TP) U1.U6(IO220)
IO221: TP221.1(TP) U1.U7(IO221)
IO222: TP222.1(TP) U1.U9(IO222)
IO223: TP223.1(TP) U1.V1(IO223)
IO224: TP224.1(TP) U1.V2(IO224)
IO225: TP225.1(TP) U1.V3(IO225)
IO226: TP226.1(TP) U1.V4(IO226)
IO227: TP227.1(TP) U1.V6(IO227)
IO228: TP228.1(TP) U1.V7(IO228)
IO229: TP229.1(TP) U1.V8(IO229)
IO230: TP230.1(TP) U1.V9(IO230)
IO231: TP231.1(TP) U1.V10(IO231)
IO232: TP232.1(TP) U1.W1(IO232)
IO233: TP233.1(TP) U1.W3(IO233)
IO234: TP234.1(TP) U1.W4(IO234)
IO235: TP235.1(TP) U1.W5(IO235)
IO236: TP236.1(TP) U1.W6(IO236)
IO237: TP237.1(TP) U1.W8(IO237)
IO238: TP238.1(TP) U1.W9(IO238)
IO239: TP239.1(TP) U1.W10(IO239)
IO240: TP240.1(TP) U1.W12(IO240)
IO241: TP241.1(TP) U1.W13(IO241)
IO242: TP242.1(TP) U1.W14(IO242)
IO243: TP243.1(TP) U1.W15(IO243)
IO244: TP244.1(TP) U1.W16(IO244)
IO245: TP245.1(TP) U1.W18(IO245)
IO246: TP246.1(TP) U1.W19(IO246)
IO247: TP247.1(TP) U1.W20(IO247)
IO248: TP248.1(TP) U1.Y1(IO248)
IO249: TP249.1(TP) U1.Y2(IO249)
IO250: TP250.1(TP) U1.Y3(IO250)
IO251: TP251.1(TP) U1.Y5(IO251)
IO252: TP252.1(TP) U1.Y6(IO252)
IO253: TP253.1(TP) U1.Y7(IO253)
IO254: TP254.1(TP) U1.Y8(IO254)
IO255: TP255.1(TP) U1.Y10(IO255)
IO256: TP256.1(TP) U1.Y11(IO256)
IO257: TP257.1(TP) U1.Y12(IO257)
IO258: TP258.1(TP) U1.Y13(IO258)
IO259: TP259.1(TP) U1.Y15(IO259)
IO260: TP260.1(TP) U1.Y16(IO260)
IO261: TP261.1(TP) U1.Y17(IO261)
IO262: TP262.1(TP) U1.Y18(IO262)
IO263: TP263.1(TP) U1.Y20(IO263)
IO264: TP264.1(TP) U1.Y21(IO264)
IO265: TP265.1(TP) U1.AA2(IO265)
IO266: TP266.1(TP) U1.AA3(IO266)
IO267: TP267.1(TP) U1.AA4(IO267)
IO268: TP268.1(TP) U1.AA5(IO268)
IO269: TP269.1(TP) U1.AA7(IO269)
IO270: TP270.1(TP) U1.AA8(IO270)
IO271: TP271.1(TP) U1.AA9(IO271)
IO272: TP272.1(TP) U1.AA10(IO272)
IO273: TP273.1(TP) U1.AA12(IO273)
IO274: TP274.1(TP) U1.AA13(IO274)
IO275: TP275.1(TP) U1.AA14(IO275)
IO276: TP276.1(TP) U1.AA15(IO276)
IO277: TP277.1(TP) U1.AA17(IO277)
IO278: TP278.1(TP) U1.AA18(IO278)
IO279: TP279.1(TP) U1.AA19(IO279)
IO280: TP280.1(TP) U1.AA20(IO280)
IO281: TP281.1(TP) U1.AB1(IO281)
IO282: TP282.1(TP) U1.AB2(IO282)
IO283: TP283.1(TP) U1.AB4(IO283)
IO284: TP284.1(TP) U1.AB5(IO284)
IO285: TP285.1(TP) U1.AB6(IO285)
IO286: TP286.1(TP) U1.AB7(IO286)
IO287: TP287.1(TP) U1.AB9(IO287)
IO288: TP288.1(TP) U1.AB10(IO288)
IO289: TP289.1(TP) U1.AB11(IO289)
IO290: TP290.1(TP) U1.AB12(IO290)
IO291: TP291.1(TP) U1.AB14(IO291)
IO292: TP292.1(TP) U1.AB15(IO292)
IO293: TP293.1(TP) U1.AB16(IO293)
IO294: TP294.1(TP) U1.AB17(IO294)
IO295: TP295.1(TP) U1.AB19(IO295)
IO296: TP296.1(TP) U1.AB20(IO296)
IO297: TP297.1(TP) U1.AB21(IO297)
IO298: TP298.1(TP) U1.AC1(IO298)
IO299: TP299.1(TP) U1.AC2(IO299)
IO300: TP300.1(TP) U1.AC3(IO300)
IO301: TP301.1(TP) U1.AC4(IO301)
IO302: TP302.1(TP) U1.AC6(IO302)
IO303: TP303.1(TP) U1.AC7(IO303)
IO304: TP304.1(TP) U1.AC8(IO304)
IO305: TP305.1(TP) U1.AC9(IO305)
IO306: TP306.1(TP) U1.AC11(IO306)
IO307: TP307.1(TP) U1.AC12(IO307)
IO308: TP308.1(TP) U1.AC13(IO308)
IO309: TP309.1(TP) U1.AC14(IO309)
IO310: TP310.1(TP) U1.AC16(IO310)
IO311: TP311.1(TP) U1.AC17(IO311)
IO312: TP312.1(TP) U1.AC18(IO312)
IO313: TP313.1(TP) U1.AC19(IO313)
IO314: TP314.1(TP) U1.AC21(IO314)
IO315: TP315.1(TP) U1.AD1(IO315)
